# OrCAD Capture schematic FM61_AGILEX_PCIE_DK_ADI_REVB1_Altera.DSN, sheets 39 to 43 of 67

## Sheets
39 Clock 2: size B
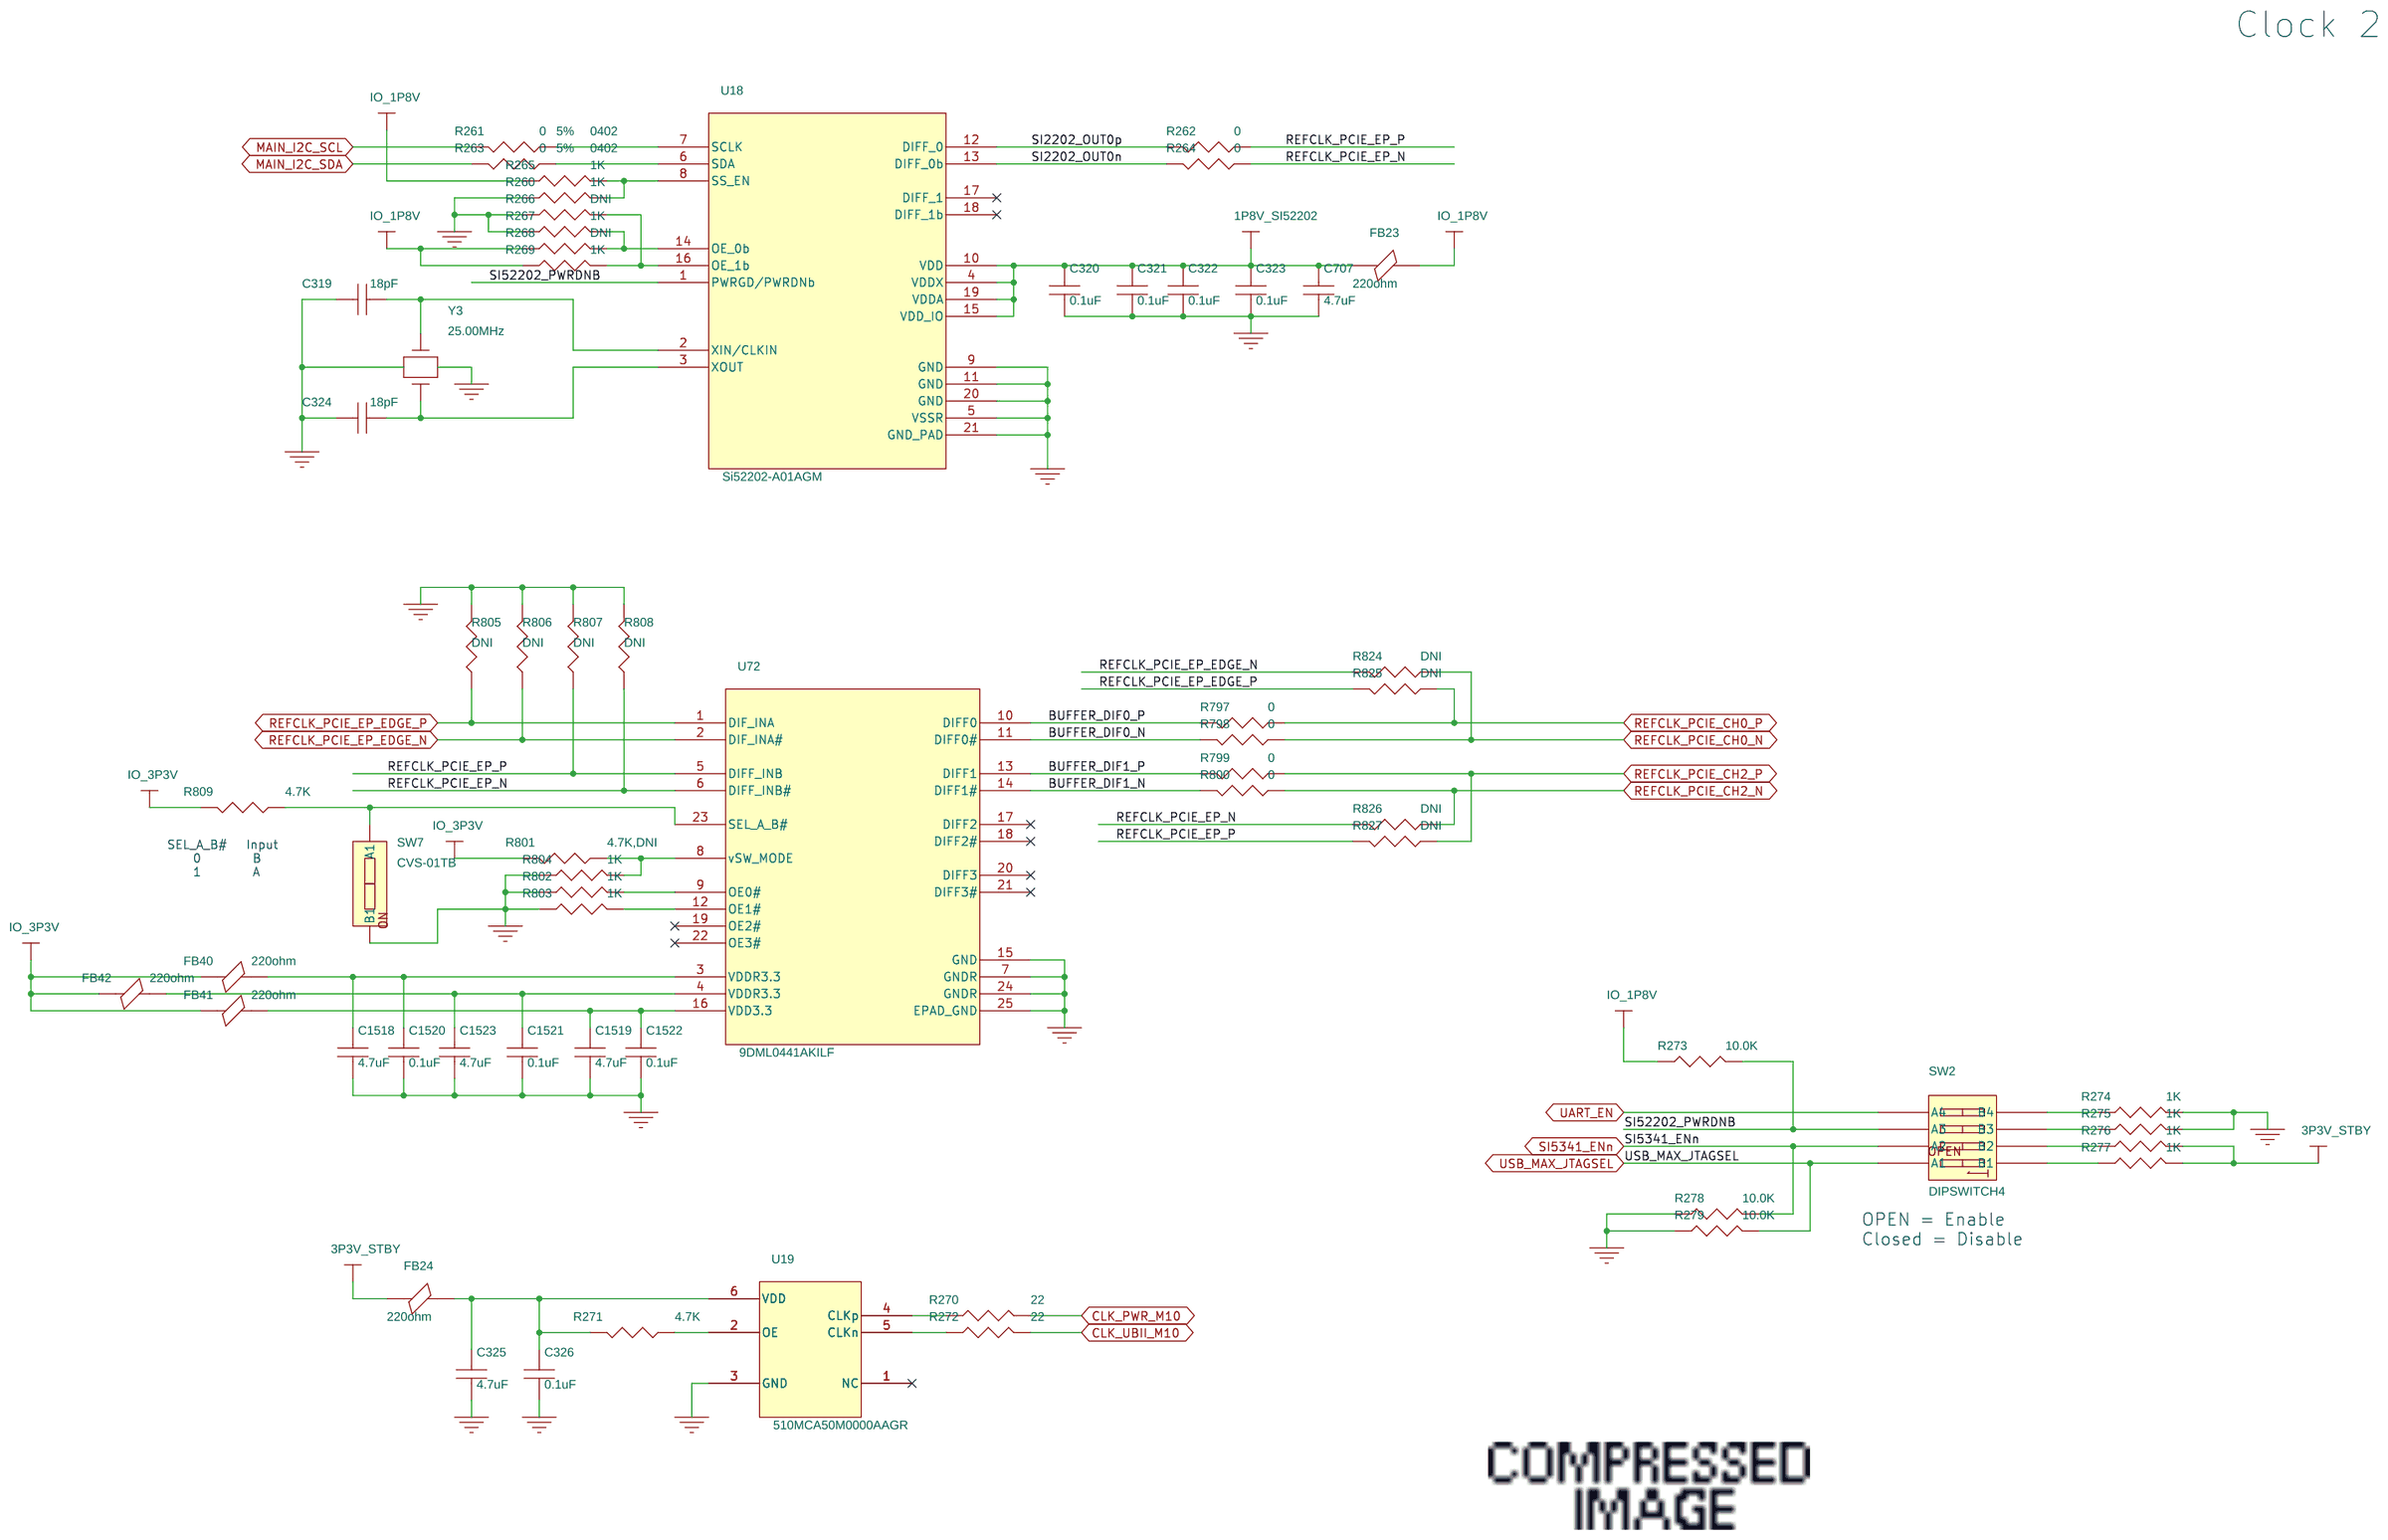
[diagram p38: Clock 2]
40 I2C And PMBUS: size B
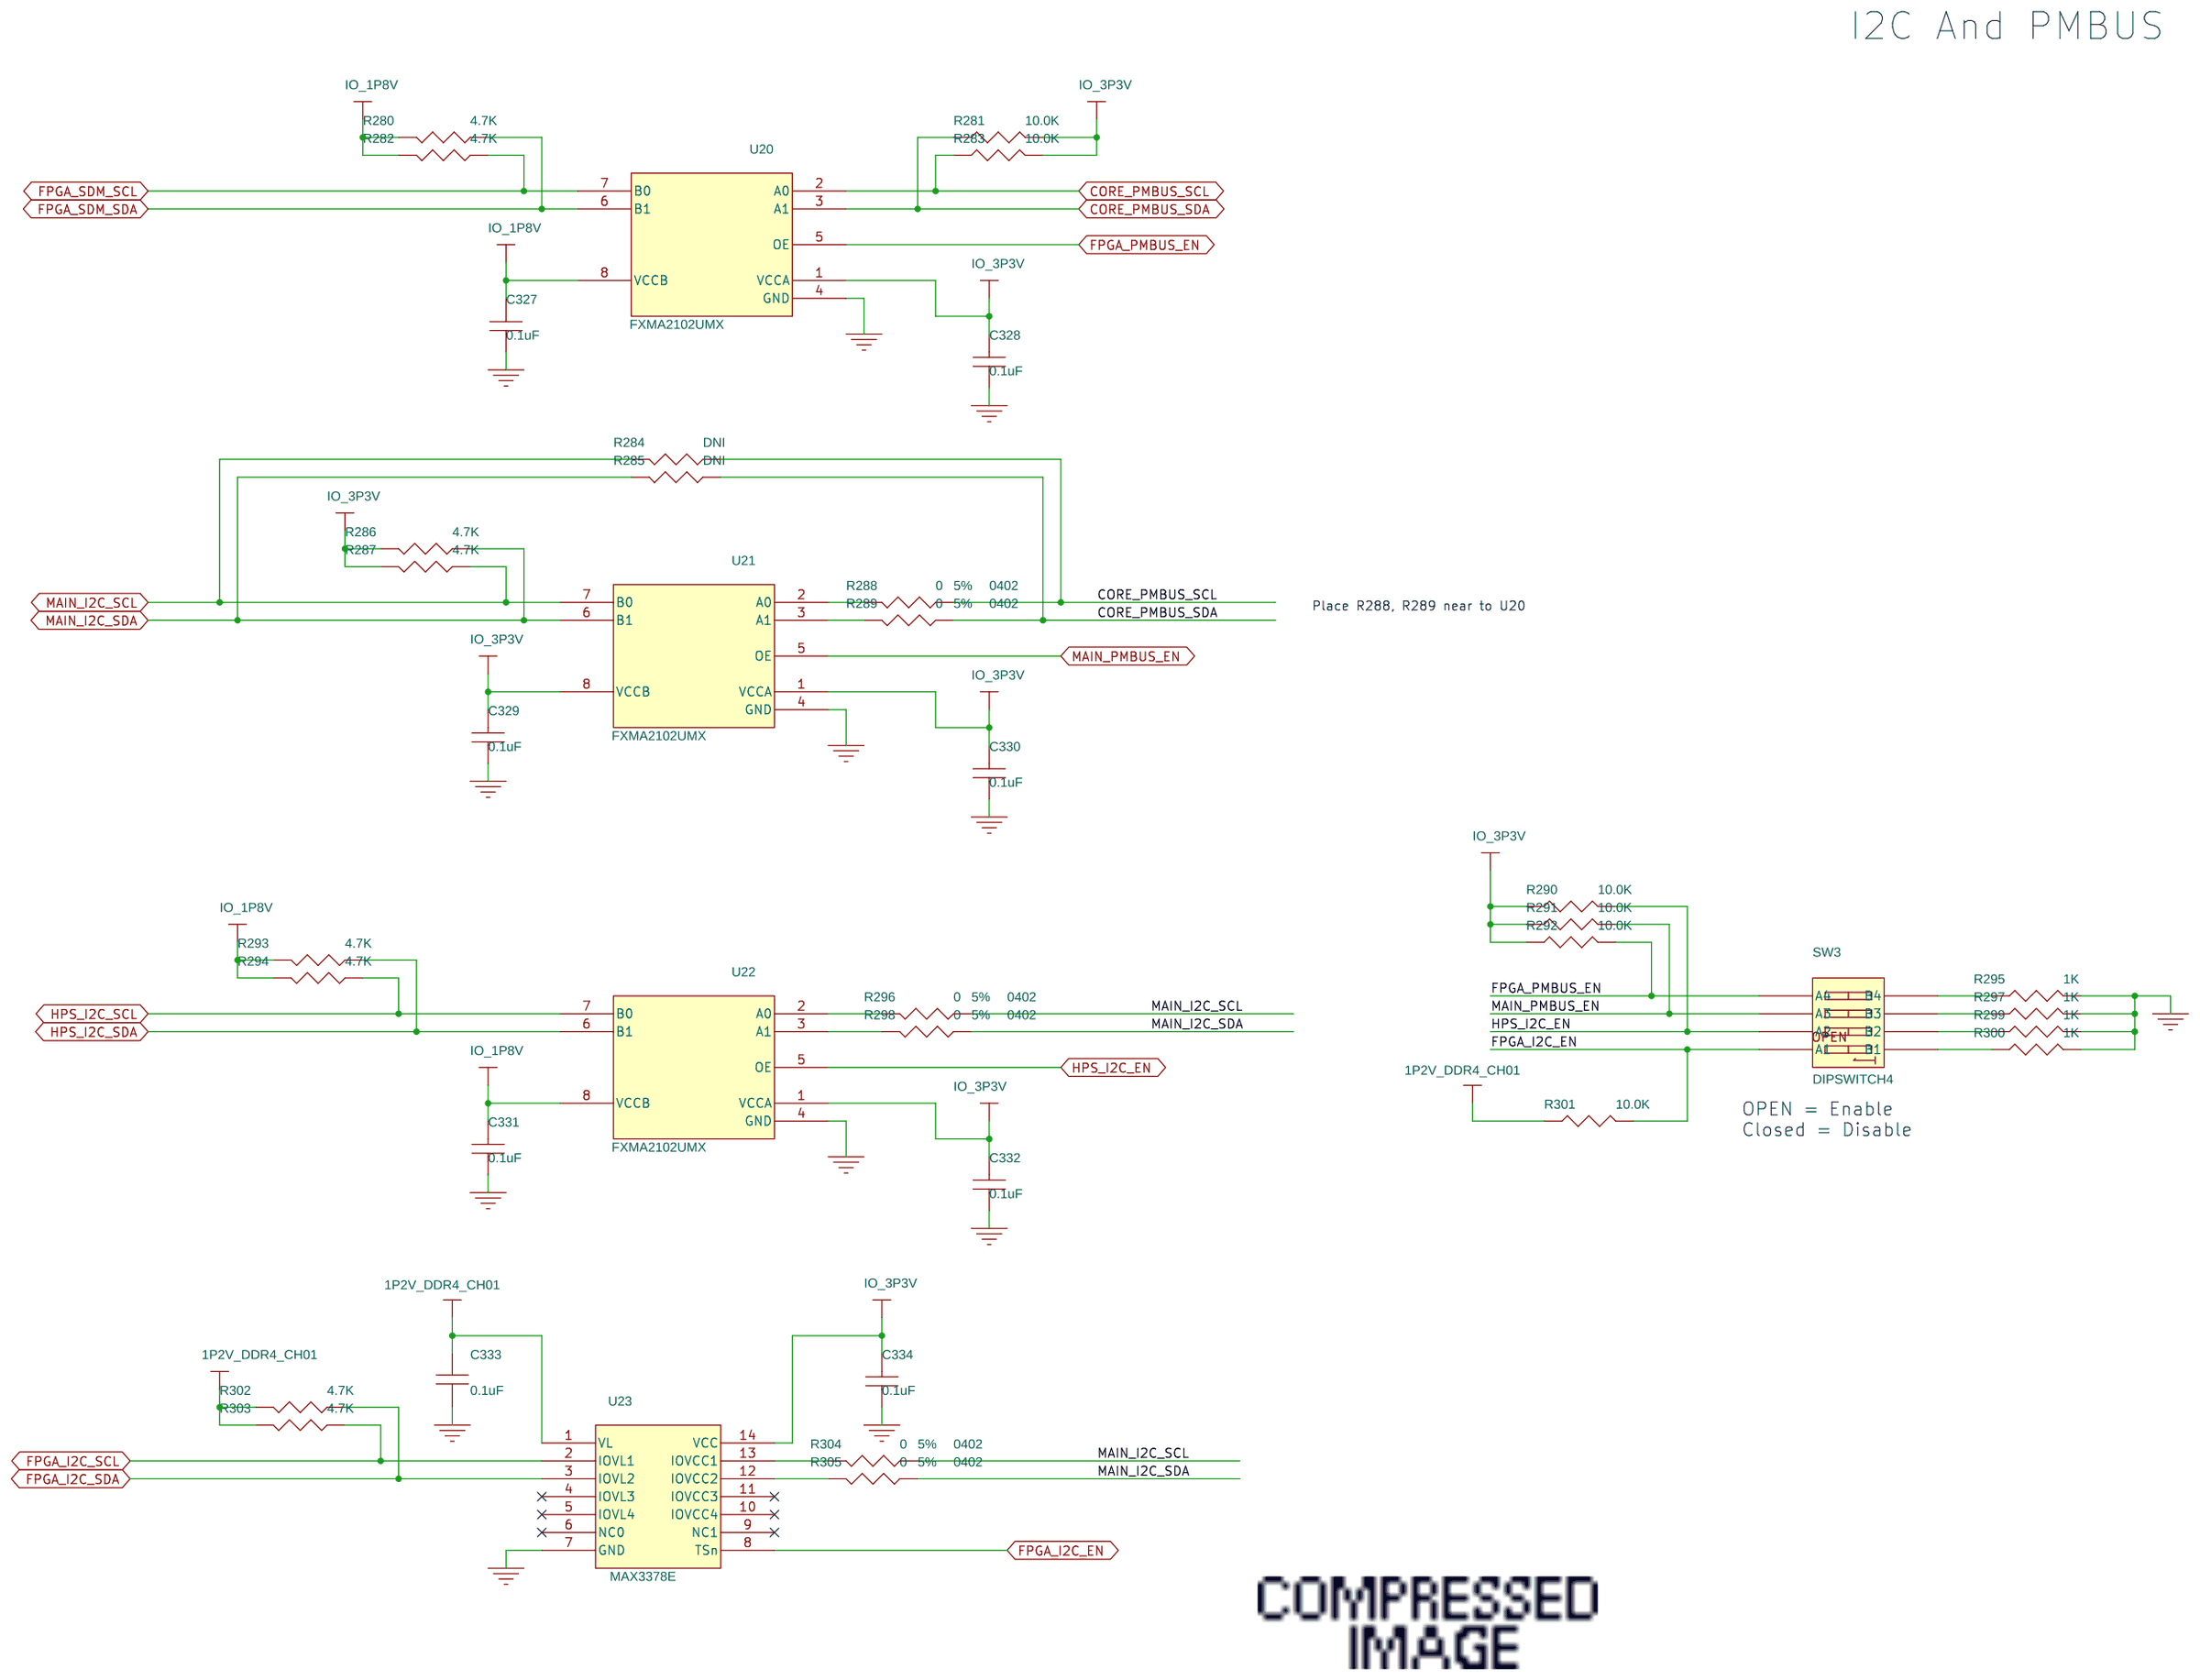
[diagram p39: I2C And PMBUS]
41 LEDs And  PushButtons: size B
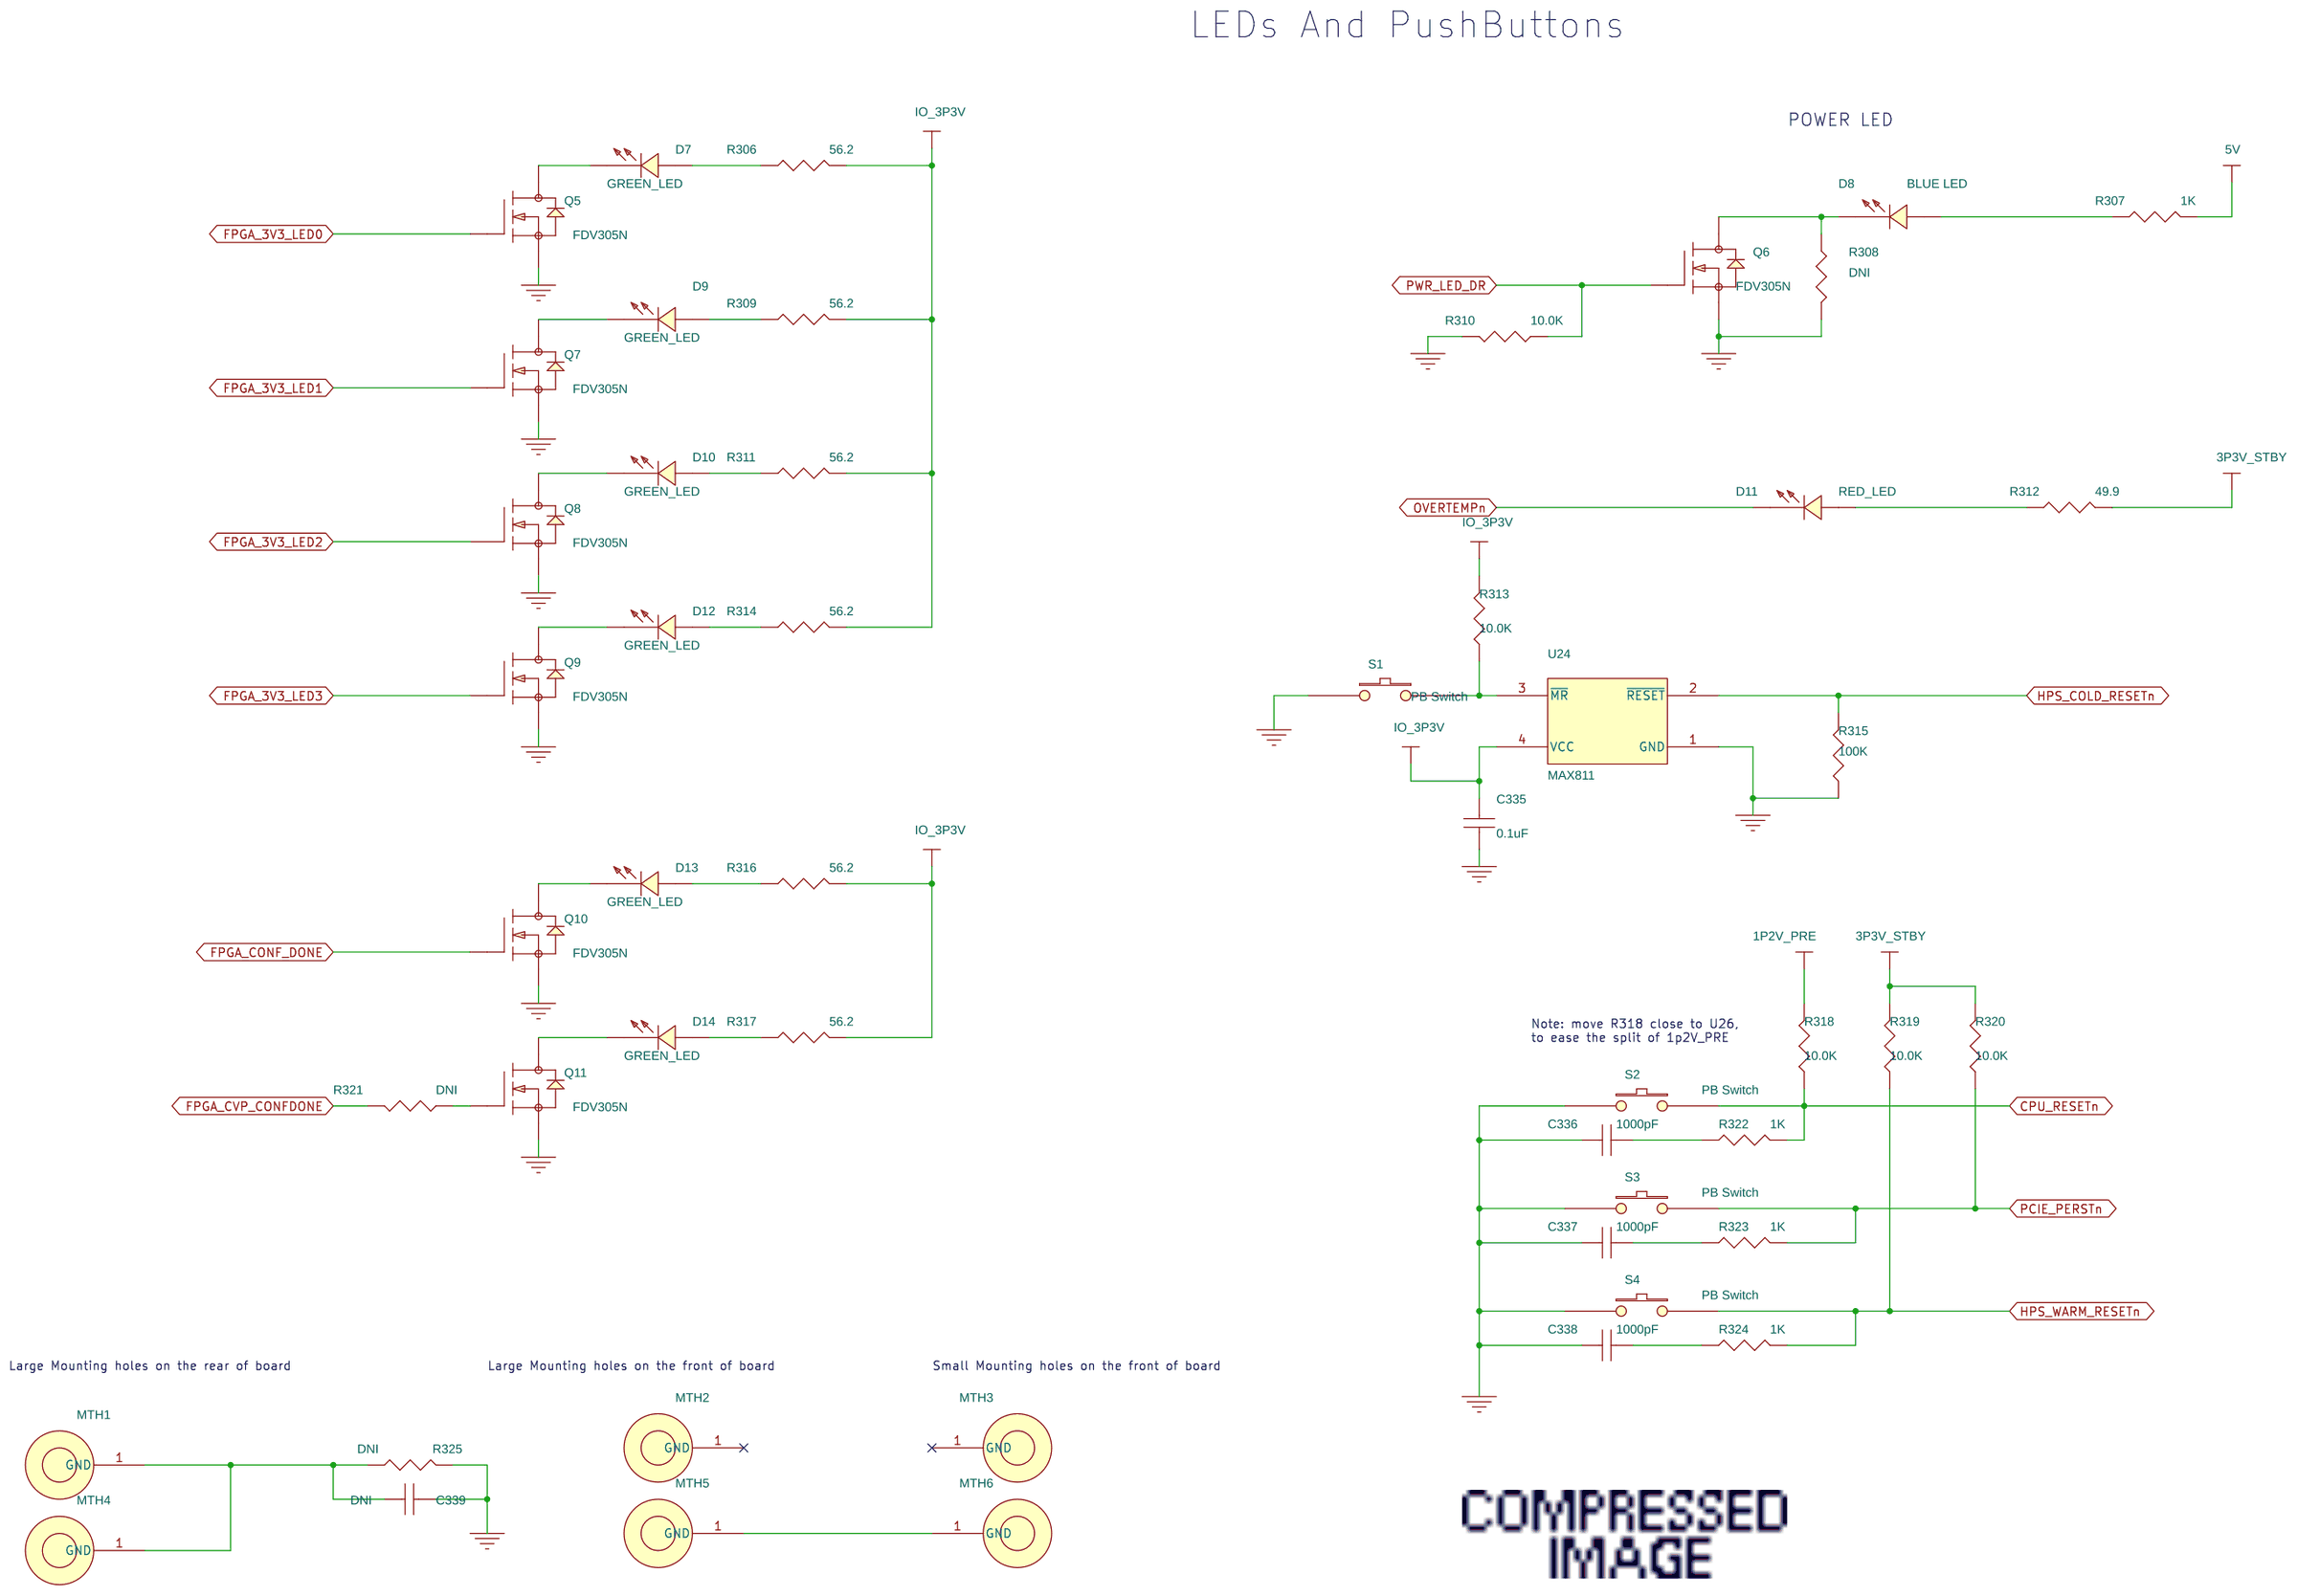
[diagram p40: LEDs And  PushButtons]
42 LEDs For QSFPDD: size B
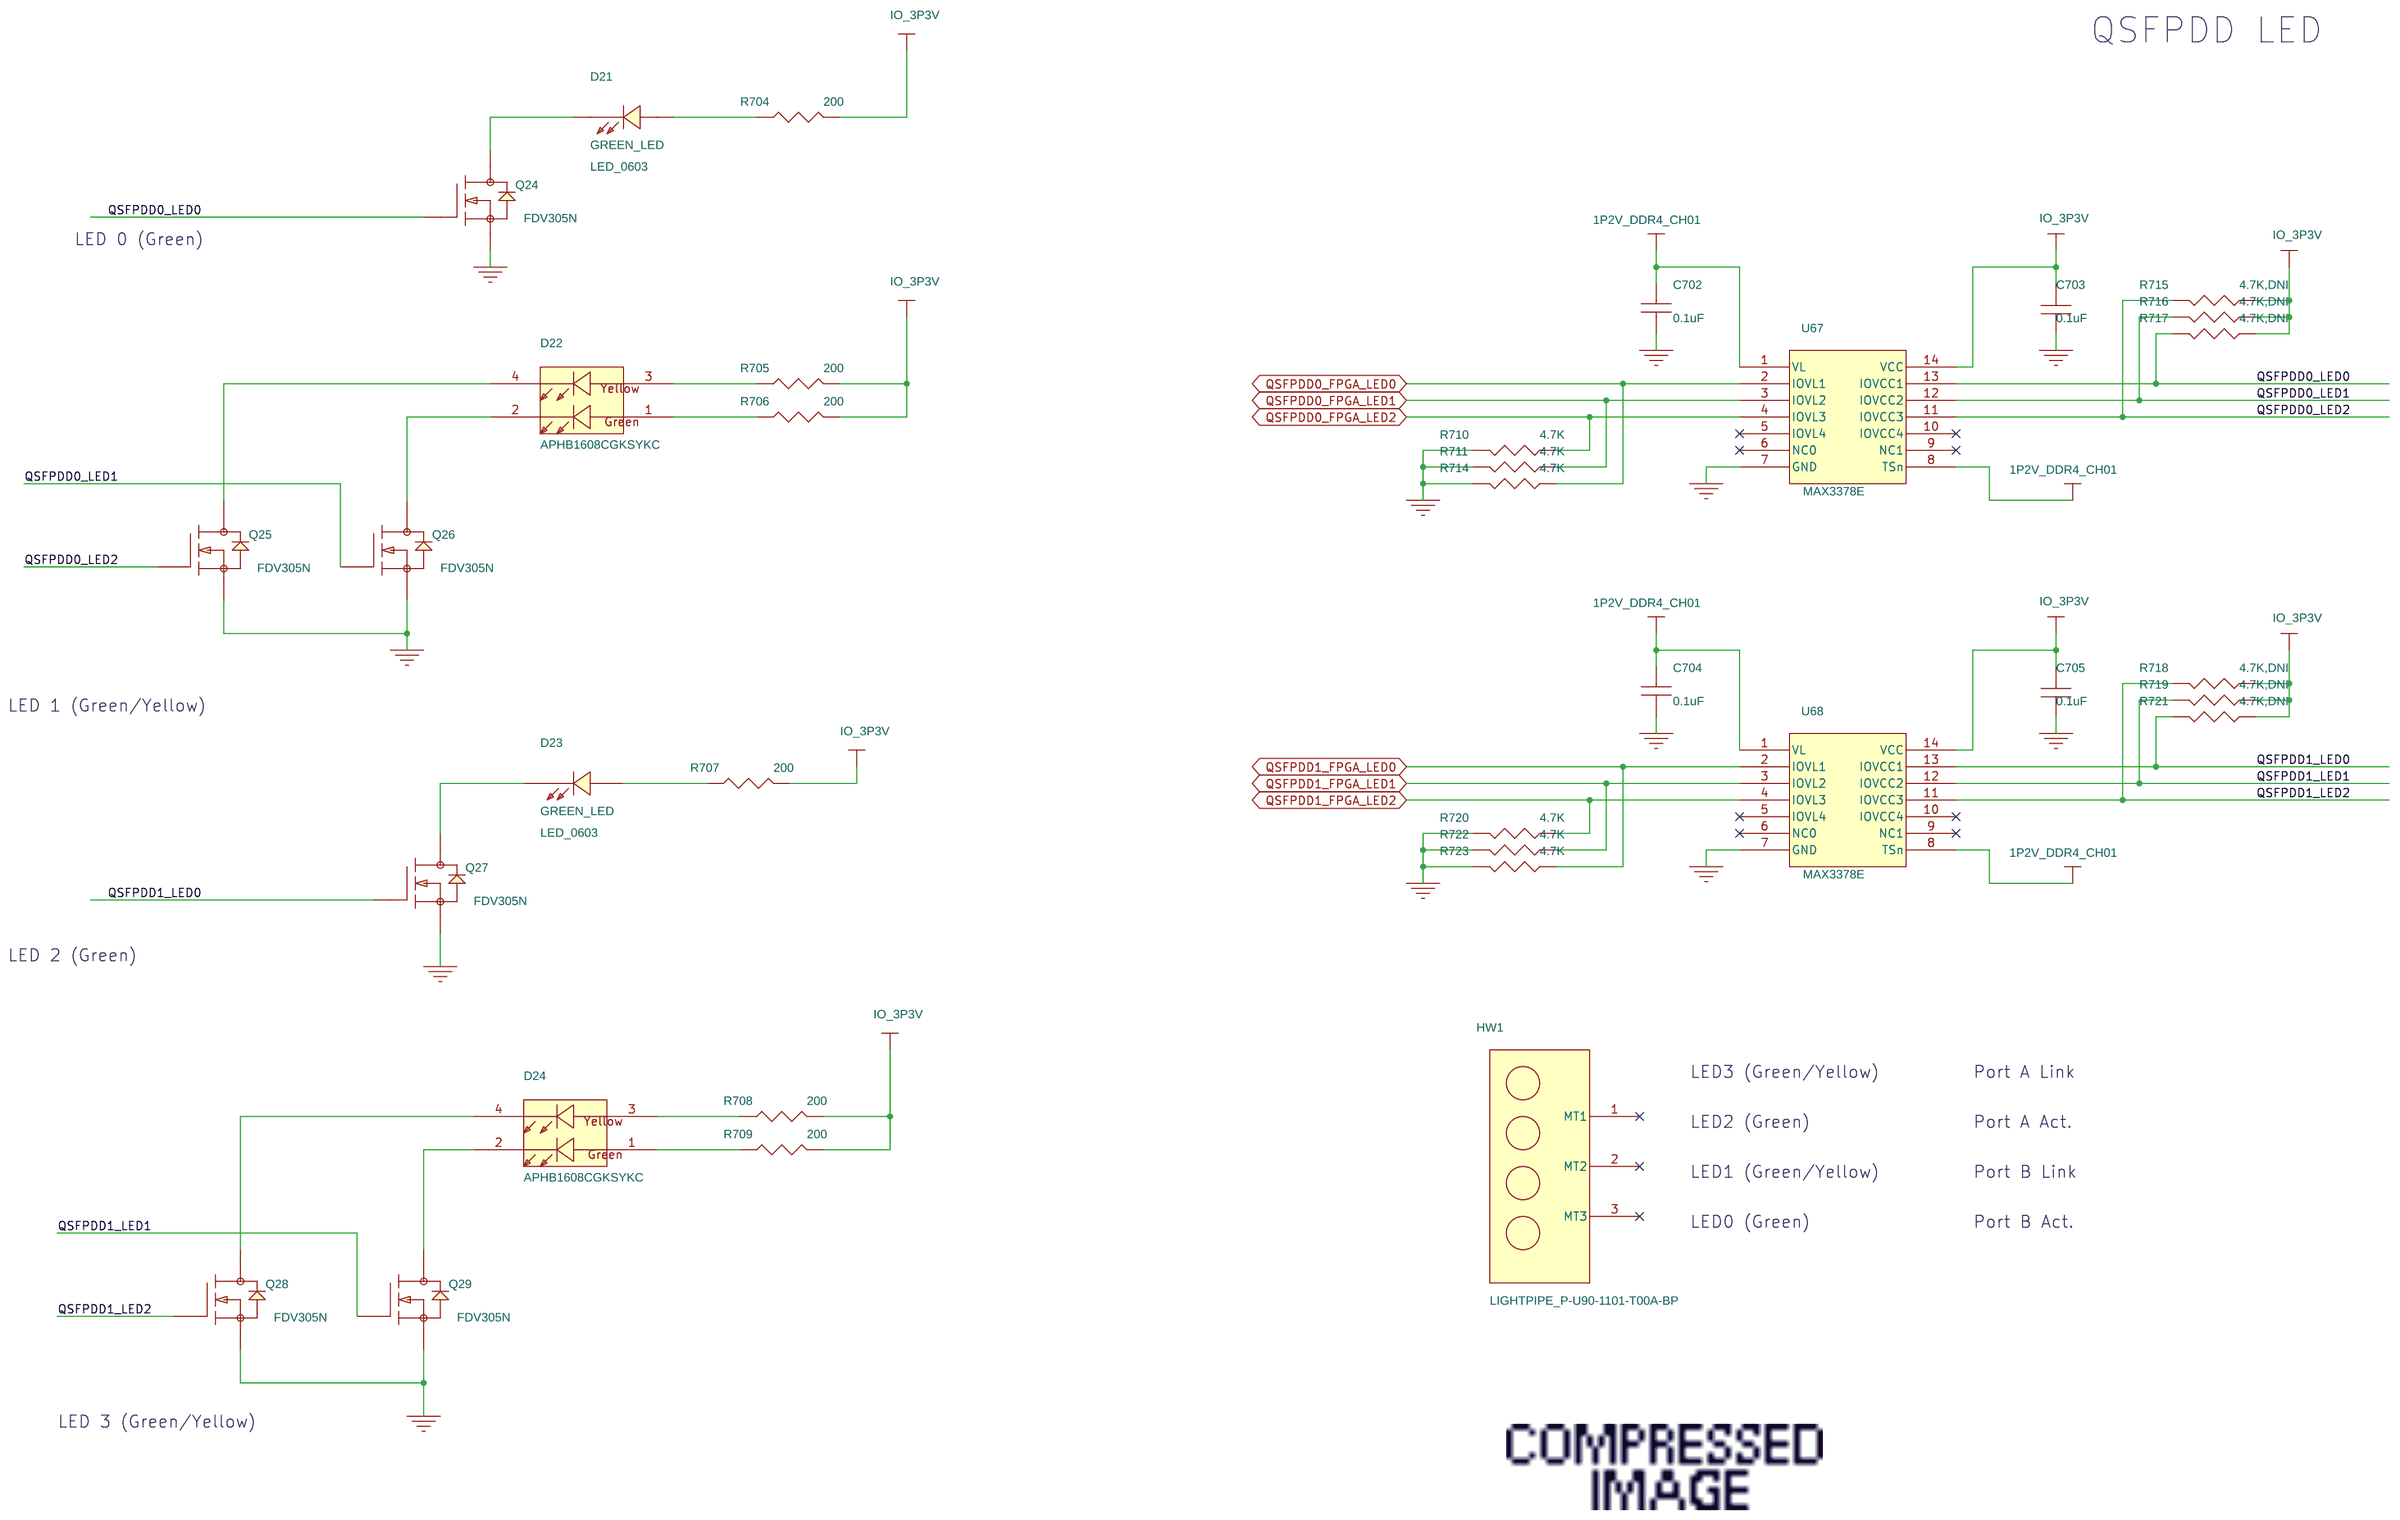
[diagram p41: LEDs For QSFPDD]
43 MAX10 - USB Blaster II -1: size B
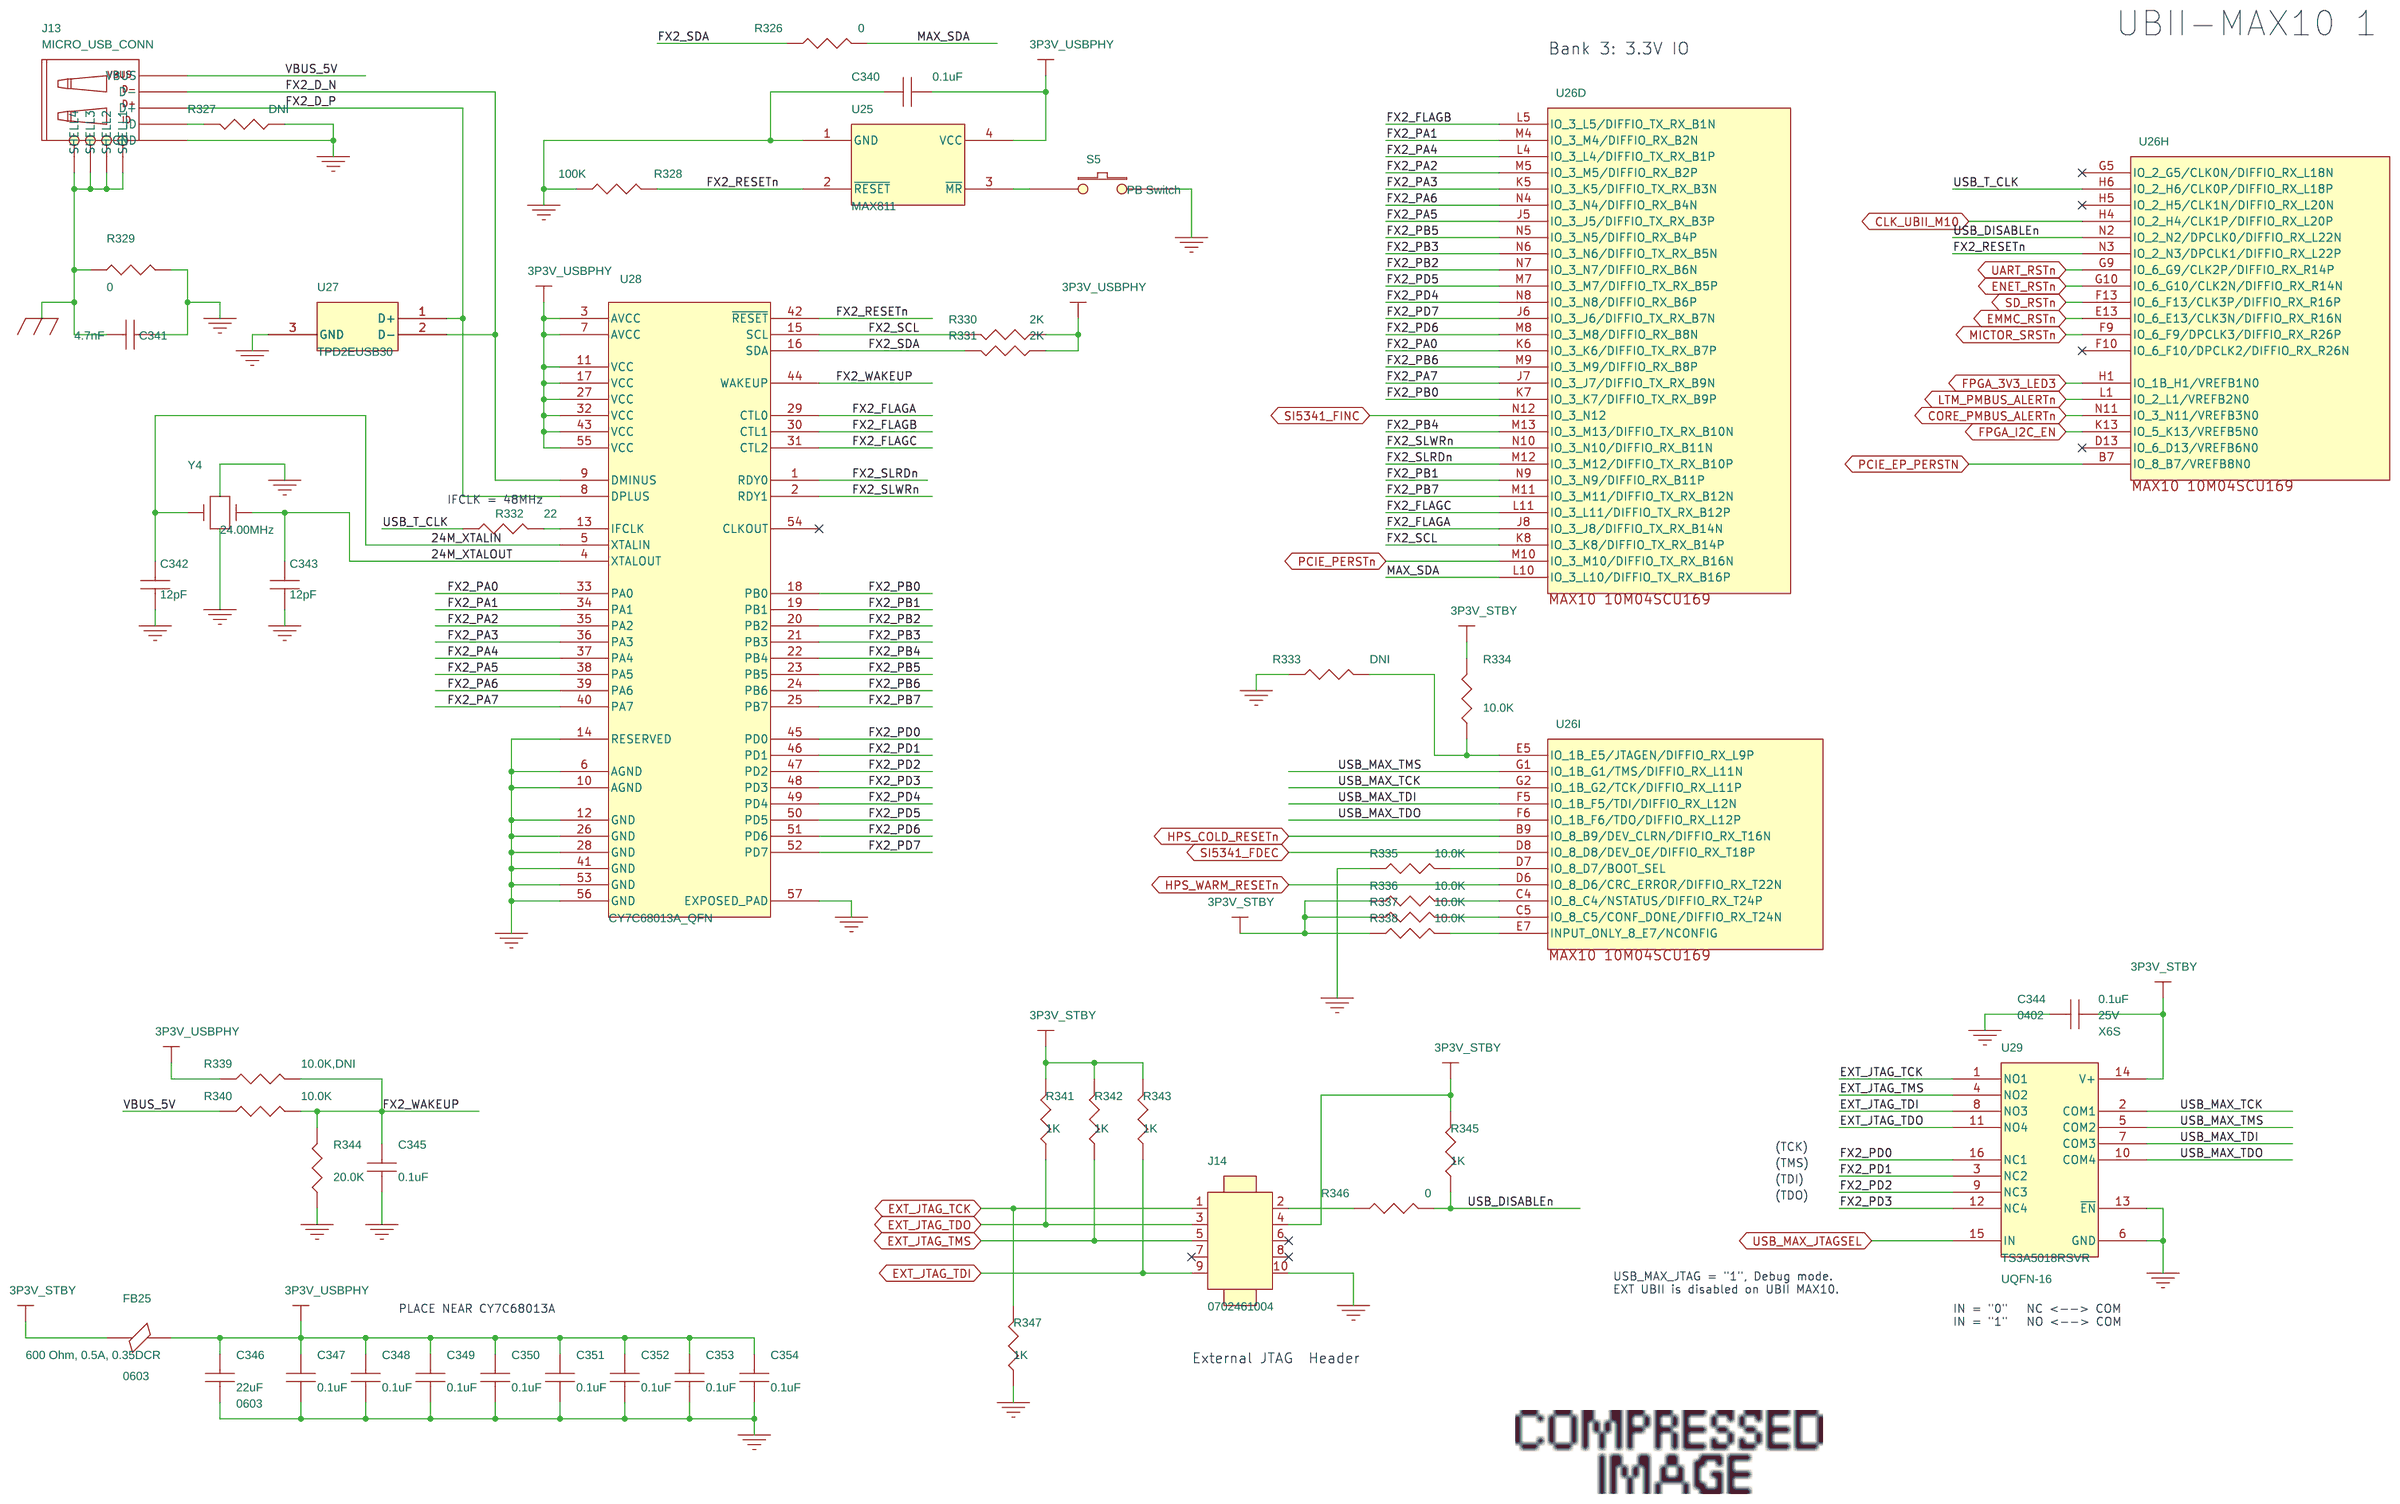
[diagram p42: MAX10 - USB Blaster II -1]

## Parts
sheet Clock 2
C319  18pF  [0402]
C320  0.1uF  [0402]
C321  0.1uF  [0402]
C322  0.1uF  [0402]
C323  0.1uF  [0402]
C324  18pF  [0402]
C325  4.7uF  [0402]
C326  0.1uF  [0402]
C707  4.7uF  [0402]
C1518  4.7uF  [0402]
C1519  4.7uF  [0402]
C1520  0.1uF  [0402]
C1521  0.1uF  [0402]
C1522  0.1uF  [0402]
C1523  4.7uF  [0402]
FB23  220ohm  [0402]
FB24  220ohm  [0402]
FB40  220ohm  [0402]
FB41  220ohm  [0402]
FB42  220ohm  [0402]
R260  1K  [0402]
R261  0  [0402]
R262  0  [0402]
R263  0  [0402]
R264  0  [0402]
R265  1K  [0402]
R266  DNI  [0402]
R267  1K  [0402]
R268  DNI  [0402]
R269  1K  [0402]
R270  22  [0402]
R271  4.7K  [0402]
R272  22  [0402]
R273  10.0K  [0402]
R274  1K  [0402]
R275  1K  [0402]
R276  1K  [0402]
R277  1K  [0402]
R278  10.0K  [0402]
R279  10.0K  [0402]
R797  0  [0402]
R798  0  [0402]
R799  0  [0402]
R800  0  [0402]
R801  4.7K,DNI  [0402]
R802  1K  [0402]
R803  1K  [0402]
R804  1K  [0402]
R805  DNI  [0402]
R806  DNI  [0402]
R807  DNI  [0402]
R808  DNI  [0402]
R809  4.7K  [0402]
R824  DNI  [0402]
R825  DNI  [0402]
R826  DNI  [0402]
R827  DNI  [0402]
SW2  DIPSWITCH4  [DIPSWITCH_SMT_QUAD]
SW7  CVS-01TB  [DIPSWITCH_SMT_SINGLE]
U18  Si52202-A01AGM  [Si52202]
U19  510MCA50M0000AAGR  [si510]
U72  9DML0441AKILF  [24-VFQFPN]
Y3  25.00MHz  [XTAL_FA-128]
sheet I2C And PMBUS
C327  0.1uF  [0402]
C328  0.1uF  [0402]
C329  0.1uF  [0402]
C330  0.1uF  [0402]
C331  0.1uF  [0402]
C332  0.1uF  [0402]
C333  0.1uF  [0402]
C334  0.1uF  [0402]
R280  4.7K  [0402]
R281  10.0K  [0402]
R282  4.7K  [0402]
R283  10.0K  [0402]
R284  DNI  [0402]
R285  DNI  [0402]
R286  4.7K  [0402]
R287  4.7K  [0402]
R288  0  [0402]
R289  0  [0402]
R290  10.0K  [0402]
R291  10.0K  [0402]
R292  10.0K  [0402]
R293  4.7K  [0402]
R294  4.7K  [0402]
R295  1K  [0402]
R296  0  [0402]
R297  1K  [0402]
R298  0  [0402]
R299  1K  [0402]
R300  1K  [0402]
R301  10.0K  [0402]
R302  4.7K  [0402]
R303  4.7K  [0402]
R304  0  [0402]
R305  0  [0402]
SW3  DIPSWITCH4  [DIPSWITCH_SMT_QUAD]
U20  FXMA2102UMX  [UMLP]
U21  FXMA2102UMX  [UMLP]
U22  FXMA2102UMX  [UMLP]
U23  MAX3378E  [TSSOP-14]
sheet LEDs And  PushButtons
C335  0.1uF  [0402]
C336  1000pF  [0402]
C337  1000pF  [0402]
C338  1000pF  [0402]
C339  DNI  [1206]
D7  GREEN_LED  [LED_0603]
D8  BLUE LED  [LED_0603]
D9  GREEN_LED  [LED_0603]
D10  GREEN_LED  [LED_0603]
D11  RED_LED  [LED_0603]
D12  GREEN_LED  [LED_0603]
D13  GREEN_LED  [LED_0603]
D14  GREEN_LED  [LED_0603]
MTH1  MT_HOLE_GND  [MH_D125C175T_TB315]
MTH2  MT_HOLE_GND  [MH_D125C175T_TB315]
MTH3  MT_HOLE_GND  [MT_HOLE]
MTH4  MT_HOLE_GND  [MH_D125C175T_TB315]
MTH5  MT_HOLE_GND  [MH_D125C175T_TB315]
MTH6  MT_HOLE_GND  [MT_HOLE]
Q5  FDV305N  [SOT23]
Q6  FDV305N  [SOT23]
Q7  FDV305N  [SOT23]
Q8  FDV305N  [SOT23]
Q9  FDV305N  [SOT23]
Q10  FDV305N  [SOT23]
Q11  FDV305N  [SOT23]
R306  56.2  [0402]
R307  1K  [0402]
R308  DNI  [0402]
R309  56.2  [0402]
R310  10.0K  [0402]
R311  56.2  [0402]
R312  49.9  [0402]
R313  10.0K  [0402]
R314  56.2  [0402]
R315  100K  [0402]
R316  56.2  [0402]
R317  56.2  [0402]
R318  10.0K  [0402]
R319  10.0K  [0402]
R320  10.0K  [0402]
R321  DNI  [0402]
R322  1K  [0402]
R323  1K  [0402]
R324  1K  [0402]
R325  DNI  [0402]
S1  PB Switch  [WURTH_6X3P5_TACT_SWITCH]
S2  PB Switch  [WURTH_6X3P5_TACT_SWITCH]
S3  PB Switch  [WURTH_6X3P5_TACT_SWITCH]
S4  PB Switch  [WURTH_6X3P5_TACT_SWITCH]
U24  MAX811  [SOT-143]
sheet LEDs For QSFPDD
C702  0.1uF  [0402]
C703  0.1uF  [0402]
C704  0.1uF  [0402]
C705  0.1uF  [0402]
D21  GREEN_LED  [LED_0603]
D22  APHB1608CGKSYKC  [LED0603_4Pin_APHB1608]
D23  GREEN_LED  [LED_0603]
D24  APHB1608CGKSYKC  [LED0603_4Pin_APHB1608]
HW1  LIGHTPIPE_P-U90-1101-T00A-BP  [LIGHTPIPE_P-U90-1101-T00A-BP]
Q24  FDV305N  [SOT23]
Q25  FDV305N  [SOT23]
Q26  FDV305N  [SOT23]
Q27  FDV305N  [SOT23]
Q28  FDV305N  [SOT23]
Q29  FDV305N  [SOT23]
R704  200  [0402]
R705  200  [0402]
R706  200  [0402]
R707  200  [0402]
R708  200  [0402]
R709  200  [0402]
R710  4.7K  [0402]
R711  4.7K  [0402]
R714  4.7K  [0402]
R715  4.7K,DNI  [0402]
R716  4.7K,DNI  [0402]
R717  4.7K,DNI  [0402]
R718  4.7K,DNI  [0402]
R719  4.7K,DNI  [0402]
R720  4.7K  [0402]
R721  4.7K,DNI  [0402]
R722  4.7K  [0402]
R723  4.7K  [0402]
U67  MAX3378E  [TSSOP-14]
U68  MAX3378E  [TSSOP-14]
sheet MAX10 - USB Blaster II -1
C340  0.1uF  [0402]
C341  4.7nF  [0402]
C342  12pF  [0402]
C343  12pF  [0402]
C344  0.1uF  [0402]
C345  0.1uF  [0402]
C346  22uF  [0603]
C347  0.1uF  [0402]
C348  0.1uF  [0402]
C349  0.1uF  [0402]
C350  0.1uF  [0402]
C351  0.1uF  [0402]
C352  0.1uF  [0402]
C353  0.1uF  [0402]
C354  0.1uF  [0402]
FB25  600 Ohm, 0.5A, 0.35DCR  [0603]
J13  MICRO_USB_CONN  [molex-micro-usb-47589-001]
J14  0702461004  [MOLEX_0702461004]
R326  0  [0402]
R327  DNI  [0402]
R328  100K  [0402]
R329  0  [0402]
R330  2K  [0402]
R331  2K  [0402]
R332  22  [0402]
R333  DNI  [0402]
R334  10.0K  [0402]
R335  10.0K  [0402]
R336  10.0K  [0402]
R337  10.0K  [0402]
R338  10.0K  [0402]
R339  10.0K,DNI  [0402]
R340  10.0K  [0402]
R341  1K  [0402]
R342  1K  [0402]
R343  1K  [0402]
R344  20.0K  [0402]
R345  1K  [0402]
R346  0  [0402]
R347  1K  [0402]
S5  PB Switch  [WURTH_6X3P5_TACT_SWITCH]
U25  MAX811  [SOT-143]
U26  10M04SCU169  [BGA169-0R80-11X11]  (sections A,B,C,D,E,F,G,H,I,J)
U27  TPD2EUSB30  [DRT]
U28  CY7C68013A_QFN  [QFN56]
U29  TS3A5018RSVR  [UQFN-16]
Y4  24.00MHz  [XTAL_FA-128]

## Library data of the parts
C319 C324 = CAP: CAP - CERAMIC, 18PF, 5%, 50V, 0402, NPO; AGILE_LINK: http://sj-agile9app/Agile/PLMServlet?action=OpenEmailObject&classid=10000&objid=213459014; IPN: H90899-001; Item Num: P03-15092R; Lead Free Status: Lead Free; MFR_LIFECYCLE: Active; Manufacturer: Panasonic; Manufacturer Part Num: ECJ-0EC1H180J; Num Pins: 2; PART_SUBCLASS: CAPACITORS; RoHS Compliant: Yes
C320-C323 C335 C345 C347-C354 = CAP: CAPC,Y5V,0402,0.1UF,25V,+80/-20%; AGILE_LINK: http://sj-agile9app/Agile/PLMServlet?action=OpenEmailObject&classid=10000&objid=213459527; IPN: K13560-001; Item Num: P03-15057R; LIFECYCLE_PHASE: Active; Lead Free Status: Lead Free; MFR_LIFECYCLE: Active; Manufacturer: Murata; Manufacturer Part Num: GRM155F51E104ZA01D; Num Pins: 2; PART_SUBCLASS: CAPACITORS; Part Class: CAPACITORS; RATED_VOLTAGE: 25V; RoHS Compliant: RoHS Compliant; TOLERANCE: +80%/-20%
C325 C707 C1518 C1519 C1523 = CAP: CAP - CER 4.7UF, +/-20%, 6.3V, X5R, 0402; IPN: H68701-001; Item Num: P03-17432R; Manufacturer: Murata; Manufacturer Part Num: GRM155R60J475ME87D; Tolerance: +/-20%; Voltage: 6.3V
C326 C1520-C1522 = CAP: CAP CER 0.1UF 25V 20% X7R 0402; AGILE_LINK: http://sj-agile9app/Agile/PLMServlet?action=OpenEmailObject&classid=10000&objid=213459527; IPN: K13660-001; Item Num: P03-17618R; LIFECYCLE_PHASE: Active; Lead Free Status: Lead Free; MFR_LIFECYCLE: Active; Manufacturer: TDK Electronics; Manufacturer Part Num: C1005X7R1E104M; Num Pins: 2; PART_SUBCLASS: CAPACITORS; Part Class: CAPACITORS; RATED_VOLTAGE: 25V; RoHS Compliant: RoHS Compliant; TOLERANCE: +80%/-20%
FB23 FB24 FB40-FB42 = BEAD_FERRITE_SM: IND - SMD EMI FILTERS/CHIP FERRITE BEAD, 220-OHM @ 100MHZ, 0.35-OHM DCR, 0402; IPN: G79186-002; Imax (A): 300mA; Item Num: P04-17068R; Manufacturer: Wurth Elektronik; Manufacturer Part Num: 742792780; Rdc (Ohms): 350mOhm; Tolerance (%): 25%
R260 R265-R269 R274-R277 R295 R297 R299 R300 R307 R322-R324 R341-R343 R345 R347 R802-R804 = RESISTOR: RES,1.00K OHMS,1.0%,1/16W,0402; IPN: G60609-021; Item Num: P02-11372R; Lead Free Status: No; Manufacturer: Panasonic; Manufacturer Part Num: ERJ-2RKF1001X; Num Pins: 2; Part Class: Resistors
R261 R263 R288 R289 R296 R298 R304 R305 R326 R329 R346 = RESISTOR: RES ZERO OHM 1/16W 5% 0402 SMD; Altera Part No.: P02-14020R; IPN: H30887-001; Item Num: P02-14020R; Lead Free Status: No; Manufacturer: Panasonic; Manufacturer Part Num: ERJ-2GE0R00X; Num Pins: 2; Part Class: RESISTORS; RoHS Compliant: Yes; Tolerance: 5%
R262 R264 R321 R327 R797-R800 R824-R827 = RES_0_OHM_5%_1_16W_0402_SMD: IPN: H30887-001
R270 R272 R332 = RESISTOR: RES, 22 OHMS, 5%, 1/16W, 0402; AGILE_LINK: http://sj-agile9app/Agile/PLMServlet?action=OpenEmailObject&classid=10000&objid=218074840; IPN: K15613-001; Item Num: P02-14098R; LIFECYCLE_PHASE: Active; MFR_LIFECYCLE: Active; Manufacturer: NIC Components Corp.; Manufacturer Part Num: NRC04J220TRF; Num Pins: 2; PART_SUBCLASS: RESISTORS; POWER: 1/16W; RoHS Compliant: RoHS Compliant; TOLERANCE: +/-5%
R271 R280 R282 R286 R287 R293 R294 R302 R303 R710 R711 R714-R723 R801 R809 = RESISTOR: RES 4.7K OHM 1/16W 5% 0402 SMD; IPN: H30885-001; Item Num: P02-14032R; Lead Free Status: No; Manufacturer: Panasonic; Manufacturer Part Num: ERJ-2GEJ472X; Manufacturer's Part No.: ERJ-2GEJ472X; Num Pins: 2; Part Class: RESISTORS; Price: 0; RoHS Compliant: Yes
R273 R278 R279 R281 R283 R290-R292 R301 R310 R313 R318-R320 R334-R338 = RESISTOR: RES,10.0K OHMS,1.0%,1/16W, 0402; AGILE_LINK: http://sj-agile9app/Agile/PLMServlet?action=OpenEmailObject&classid=10000&objid=146548997; IPN: A93548-034; Item Num: P02-11364R; LIFECYCLE_PHASE: Active; Lead Free Status: No; MFR_LIFECYCLE: Active; Manufacturer: Panasonic; Manufacturer Part Num: ERJ-2RKF1002X; Num Pins: 2; PART_SUBCLASS: RESISTORS; POWER: 1/16W; RoHS Compliant: Yes; TOLERANCE: +/-1%
R312 R805-R808 = RESISTOR: RES, 49.9 OHMS, 1%, 1/16W, 0402; IPN: K16545-001; Item Num: P02-14101R; Lead Free Status: Yes; Manufacturer: NIC Components Corp.; Manufacturer Part Num: NRC04F49R9TRF; Num Pins: 2; Part Class: Resistors; Price: 0
SW2 SW3 = SPST4: SWITCHES - 4 POS, 8 PIN, Ultra-mini SMT Half-pitch Slider DIP Switch; AGILE_LINK: http://sj-agile9app/Agile/PLMServlet?action=OpenEmailObject&classid=10000&objid=258073635; IPN: K15518-001; Item Num: P11-24098R; LIFECYCLE_PHASE: Preliminary; Lead Free Status: Not Lead Free; MFR_LIFECYCLE: Active; Manufacturer: Wurth Electronik; Manufacturer Part Num: 416131160804; Num Pins: 8; PART_SUBCLASS: SWITCHES; RoHS Compliant: RoHS Compliant
SW7 = SPST4_0: SWITCH SLIDE DIP SPST 100MA 6V; AGILE_LINK: http://sj-agile9app/Agile/PLMServlet?action=OpenEmailObject&classid=10000&objid=258073635; Agile IPN: P11-24597R; IPN: H80030-001; LIFECYCLE_PHASE: Preliminary; Lead Free Status: Not Lead Free; MFR_LIFECYCLE: Active; Manufacturer: Nidec Copal Electronics; Num Pins: 8; PART_SUBCLASS: SWITCHES; RoHS Compliant: RoHS Compliant
U18 = Si52202-A01AGM: IPN: K45431-001
U19 = Si510-DualCMOS: OSC - 50MHZ, +/-30PPM, 3.3V, DUAL CMOS (IN PHASE), CRYSTAL OSCILLATOR, SMD; IPN: K14787-001; Item Num: P13-27235R; Manufacturer: Silicon Laboratories Inc
U72 = 9DML0451AKILF: IC,CLK_GEN,24,VFQFPN,N/A,GNRTR,N/A; IPN: K46480-001
Y3 = CRYSTAL_SM_13: CRYSTAL - MINI XTL, 25.00MHZ, FREQ +/-50PPM, RANGE +/-30PPM -20~70C, 18PF, 2.0MM X 1.6MM SMD; IPN: K21427-001; Item Num: P07-19688R; Lead Free Status: Yes; MFR_LIFECYCLE: Active; Manufacturer: Epson Toyocom; Manufacturer Part Num: FA-128 25.0000MB-C; Num Pins: 4; RoHS Compliant: Yes
C327-C332 C334 C703 C705 = CAP: CAP CER 0.1UF 25V 20% X7R 0402; IPN: K13660-001; Item Num: P03-17618R; LIFECYCLE_PHASE: Active; Lead Free Status: Lead Free; Manufacturer: TDK Electronics; Manufacturer Part Num: C1005X7R1E104M; Num Pins: 2; Part Class: CAPACITORS; Price: 0; RoHS Compliant: RoHS Compliant
C333 C702 C704 = CAP: CAPC,Y5V,0402,0.1UF,25V,+80/-20%; Dielectric: Y5V; IPN: K13560-001; Item Num: P03-15057R; LIFECYCLE_PHASE: Active; Lead Free Status: Lead Free; MFR_LIFECYCLE: Active; Manufacturer: Murata; Manufacturer Part Num: GRM155F51E104ZA01D; Num Pins: 2; PART_SUBCLASS: CAPACITORS; Part Class: CAPACITORS; RATED_VOLTAGE: 25V; RoHS Compliant: RoHS Compliant; Tolerance: +80%/-20%
R284 R285 = RESISTOR: RES ZERO OHM 1/16W 5% 0402 SMD; Altera Part No.: P02-14020R; IPN: H30887-001; Item Num: P02-14020R; Lead Free Status: No; Manufacturer: Panasonic; Manufacturer Part Num: ERJ-2GE0R00X; Num Pins: 2; Part Class: RESISTORS; Price: 0; RoHS Compliant: Yes; Tolerance: 5%
U20-U22 = FXMA2102UMX: Dual Supply, 2-Bit Voltage Translator/Buffer/Repeater/Isolator for I2C application; IPN: K64812-001; Item Num: P01-17934R; Manufacturer: Fairchild
U23 U67 U68 = MAX3378E_0: IC - QUAD LOW-VOLTAGE LEVEL TRANSLATOR, +/- 15KV, ESD-PROTECTED, 1UA, 16MBPS; IPN: C34337-001; Item Num: P01-13191R; Manufacturer: Maxim; Manufacturer Part Num: MAX3378EEUD
C336-C338 = CAP: CAP CER 1000PF 50V 10% X7R 0402; Dielectric: X7R; IPN: A36096-004; Item Num: P03-17756R; LIFECYCLE_PHASE: Active; Lead Free Status: Lead Free; Manufacturer: Yageo; Manufacturer Part Num: CC0402KRX7R9BB102; Num Pins: 2; Part Class: CAPACITORS; RATED_VOLTAGE: 50V; RoHS Compliant: RoHS Compliant; Tolerance: 10%
C339 = CAP: CAP CER 1000PF 1000V X7R 1206; AGILE_LINK: http://sj-agile9app/Agile/PLMServlet?action=OpenEmailObject&classid=10000&objid=215384813; CAPACITANCE: 1000pF; IPN: K13749-001; Item Num: P03-17910R; LIFECYCLE_PHASE: Active; Lead Free Status: Lead Free; MFR_LIFECYCLE: Active; Manufacturer: Murata; Manufacturer Part Num: GRM31BR73A102KW01L; Num Pins: 2; PACKAGING: Tape & Reel (TR); PART_SUBCLASS: CAPACITORS; RATED_VOLTAGE: 1000V; RoHS Compliant: RoHS Compliant; Supplier Part Num: GRM31BR73A102KW01L; Tolerance: +/-10%
D7 D9 D10 D12-D14 = LED_WURTH: LED - BRIGHT GREEN, VF=2V, IF=0.03A, 0603; IPN: K15375-001; Item Num: P09-21344R; LIFECYCLE_PHASE: Active; Lead Free Status: Lead Free; Manufacturer: Wurth Electroniks; Manufacturer Part Num: 150060VS75000; Num Pins: 2; PART_SUBCLASS: LEDS; Part Class: LEDS; RoHS Compliant: RoHS Compliant
D8 = LED_0: LED - BLUE, VF = 3.2V, IF = 0.03A, 0603; IPN: K15378-001; Item Num: P09-21352R; Lead Free Status: No; Manufacturer: Wurth Elektronik; Manufacturer Part Num: 150060BS75000
D11 = LED_WURTH: LED -SUPER RED, VF=1.9V, IF=0.03A, 0603; IPN: K15376-001; Item Num: P09-21345R; LIFECYCLE_PHASE: Active; Lead Free Status: Lead Free; Manufacturer: Wurth Electroniks; Manufacturer Part Num: 150060SS75000; Num Pins: 2; PART_SUBCLASS: LEDS; Part Class: LEDS; RoHS Compliant: RoHS Compliant
MTH1-MTH6 = MNT_HOLE_1
Q5 Q7-Q11 Q24-Q29 = PWRMOSFET_EN_GSD_0: IC, MOSFET, N-Channel, 20V; IPN: K21465-001; Item Num: P18-31002R; Manufacturer: Fairchild; Manufacturer Part Num: FDV305N_NL
Q6 = PWRMOSFET_EN_GSD_0: IC, MOSFET, N-Channel, 20V; IPN: K21465-001; Item Num: P18-31002R; Manufacturer: Fairchild Semiconductor
R306 R309 R311 R314 R316 R317 = RESISTOR_0: RES,56.2 OHMS,1.0%,1/16W,0402; IPN: K16543-001; IPN No: K16543-001; Item Num: P02-11370R; Lead Free Status: No; Manufacturer: Panasonic; Manufacturer Part Num: ERJ-2RKF56R2X; Num Pins: 2; Part Class: RESISTORS; Price: 0; RoHS Compliant: Yes
R308 = RESISTOR: RES ZERO OHM 1/16W 5% 0402 SMD; IPN: H30887-001; Item Num: P02-14020R; Lead Free Status: No; Manufacturer: Panasonic; Manufacturer Part Num: ERJ-2GE0R00X; Num Pins: 2; Part Class: Resistors; Price: 0; RoHS Compliant: Yes
R315 R328 = RESISTOR: RES,100K OHMS,1.0%,1/16W,0402; IPN: E86804-001; Item Num: P02-11386R; Lead Free Status: No; Manufacturer: Panasonic; Manufacturer Part Num: ERJ-2RKF1003X; Num Pins: 2; POWER: 1/16W; Part Class: Resistors; Price: 0; RoHS Compliant: Yes; TOLERANCE: +/-1%
R325 = RESISTOR: RES,1M OHMS,5.0%,1/16W,0402; AGILE_LINK: http://sj-agile9app/Agile/PLMServlet?action=OpenEmailObject&classid=10000&objid=146548997; IPN: K15866-001; Item Num: P02-11390R; LIFECYCLE_PHASE: Active; Lead Free Status: No; MFR_LIFECYCLE: Active; Manufacturer: Panasonic; Manufacturer Part Num: ERJ-2GEJ105X; Num Pins: 2; PART_SUBCLASS: RESISTORS; POWER: 1/16W; RESISTANCE: 1M; RoHS Compliant: Yes; TOLERANCE: +/-5%
S1-S5 = TS-A02SA-2-S100_0: SWITCH - PUSH BUTTON 6.0X3.5MM SND; Device: S7; IPN: K11478-001; Item Num: P23-38485R; Lead Free Status: Yes; Manufacturer: Wurth Elektroniks; Manufacturer Part Num: 434121043816; Num Pins: 2; Part Class: Switches; RoHS Compliant: Yes
U24 U25 = MAX811: IC - MPU V-MONITOR 2.93V, RESET/POWER-ON RESET, SOT143-4; IPN: D16587-001; Item Num: P01-17588R; Lead Free Status: Yes; Manufacturer: Maxim Integrated Products; Manufacturer Part Num: MAX811SEUS+T; Num Pins: 4; Part Class: ICs; RoHS Compliant: Yes
D21 D23 = LED_WURTH: LED GREEN CLEAR 0603 SMD; IPN: J48659-001; Item Num: P09-21380R; Manufacturer: Kingbright; Manufacturer Part Num: APT1608CGCK; Num Pins: 2
D22 D24 = APHB1608CGKSYKC: LED,1608,SM,GRN/YEL,V,1.00,RC,2,; IPN: G93404-001; Manufacturer: Kingbright
HW1 = LIGHTPIPE_P-U90-1101-T00A-BP_2: IPN: K33020-001; Item Num: P09-21386R; Manufacturer: Amphenol; Manufacturer Part Num: P-U90-1101-T00A-BP
R704-R709 = RESISTOR: RES 200 OHM 1/16W 5% 0402 SMD; IPN: K15618-001; Item Num: P02-14026R; Manufacturer: Panasonic; Manufacturer Part Num: ERJ-2GEJ201X; Num Pins: 2; Part Class: RESISTORS; RoHS Compliant: Yes
C340 = CAP: CAPC,Y5V,0402,0.1UF,25V,+80/-20%; Dielectric: Y5V; IPN: K13560-001; Item Num: P03-15057R; LIFECYCLE_PHASE: Active; Lead Free Status: Lead Free; MFR_LIFECYCLE: Active; Manufacturer: Murata; Manufacturer Part Num: GRM155F51E104ZA01D; Num Pins: 2; PART_SUBCLASS: CAPACITORS; Part Class: CAPACITORS; RATED_VOLTAGE: 25V; RoHS Compliant: RoHS Compliant; TOLERANCE: +80%/-20%
C341 = CAP: CAP - CER 4700PF 50V 10% X7R 0402; AGILE_LINK: http://sj-agile9app/Agile/PLMServlet?action=OpenEmailObject&classid=10000&objid=215384813; IPN: A36096-066; Item Num: P03-15074R; LIFECYCLE_PHASE: Active; Lead Free Status: Lead Free; MFR_LIFECYCLE: Active; Manufacturer: Murata; Manufacturer Part Num: GRM155R71H472KA01D; Num Pins: 2; PACKAGING: Tape & Reel (TR); PART_SUBCLASS: CAPACITORS; RATED_VOLTAGE: 50V; RoHS Compliant: RoHS Compliant; Supplier Part Num: GRM155R71H472KA01D; Tolerance: +/-10%
C342 C343 = CAP: CAP - 12PF, 50V, +/-5%, CERAMIC, 0402 SMD; AGILE_LINK: http://sj-agile9app/Agile/PLMServlet?action=OpenEmailObject&classid=10000&objid=257385742; IPN: A36095-043; IPN No: A36095-043; Item Num: P03-15352R; LIFECYCLE_PHASE: Active; Lead Free Status: Lead Free; MFR_LIFECYCLE: Active; Manufacturer: Panasonic; Manufacturer Part Num: ECJ-0EC1H120J; Num Pins: 2; PART_SUBCLASS: CAPACITORS; RATED_VOLTAGE: 50V; RoHS Compliant: RoHS Compliant; TOLERANCE: +/-5%
C344 = CAP: CAP CER 0.1UF 25V X6S 0402; Dielectric: X6S; IPN: K19434-001; IPN No: K19434-001; Item Num: P03-XXXXXR; LIFECYCLE_PHASE: Active; Lead Free Status: Lead Free; Manufacturer: Murata; Manufacturer Part Num: GRM155C81E104KA12D; Num Pins: 2; Part Class: CAPACITORS; RATED_VOLTAGE: 25V; RoHS Compliant: RoHS Compliant; Tolerance: 10%
C346 = CAP: CAP CER 22UF 6.3V X6S 0603; AGILE_LINK: http://sj-agile9app/Agile/PLMServlet?action=OpenEmailObject&classid=10000&objid=257560276; IPN: H63299-001; Item Num: P03-17963R; LIFECYCLE_PHASE: Active; Lead Free Status: Lead Free; MFR_LIFECYCLE: Active; Manufacturer: Murata; Manufacturer Part Num: GRM188C80J226ME15D; Num Pins: 2; PART_SUBCLASS: CAPACITORS; RATED_VOLTAGE: 6.3V; RoHS Compliant: RoHS Compliant; TOLERANCE: 20%; Temperature Coefficient: X6S
FB25 = BEAD_FERRITE_SM: FERRITE BEAD 600 OHM, 0.5A, 0.35 DCR, 0603 1LN; IPN: G73133-001; Item Num: P04-17224R; LIFECYCLE_PHASE: Active; MFR_LIFECYCLE: Active; Manufacturer: Murata; Manufacturer Part Num: BLM18EG601SN1D; Num Pins: 2; Part Class: Inductors; RoHS Compliant: Yes
J13 = MICRO_USB_CONN: RECEPTACLE, USB 3.0, MICRO B, R/A; IPN: G68794-001; Item Num: P23-38552R; Lead Free Status: Yes; MFR_LIFECYCLE: Active; Manufacturer: Molex; Manufacturer Part Num: 47589-0001; Num Pins: 9; Part Class: Connectors; RoHS Compliant: Yes
J14 = 0702461004: IPN: K12724-001; Manufacturer Part Num: 702461004
R330 R331 = RESISTOR: RES 2K OHM 1/16W 1% 0402 SMD; IPN: J43524-001; Item Num: P02-11376R; Lead Free Status: No; Manufacturer: Panasonic; Manufacturer Part Num: ERJ-2RKF2001X; Manufacturer's Part No.: ERJ-2RKF2001X; Num Pins: 2; Part Class: RESISTORS; Price: 0; RoHS Compliant: Yes
R333 = R: RES,1.00K OHMS,1.0%,1/16W,0402; IPN: G60609-021; Item Num: P02-14274R; Lead Free Status: Yes; Manufacturer: Vishay; Manufacturer Part Num: ERJ-2RKF1001X; Num Pins: 2; Part Class: Resistors; Price: 0; RoHS Compliant: Yes
R339 R340 = RESISTOR: RES,10.0K OHMS,1.0%,1/16W, 0402; AGILE_LINK: http://sj-agile9app/Agile/PLMServlet?action=OpenEmailObject&classid=10000&objid=146548997; IPN: A93548-034; Item Num: P02-11364R; LIFECYCLE_PHASE: Active; Lead Free Status: No; MFR_LIFECYCLE: Active; Manufacturer: Panasonic; Manufacturer Part Num: ERJ-2RKF1002X; Num Pins: 2; PART_SUBCLASS: RESISTORS; POWER: 1/16W; RESISTANCE: 10K; RoHS Compliant: Yes; TOLERANCE: +/-1%
R344 = RESISTOR: RES 20.0K OHM 1/16W 1% 0402 SMD; IPN: A78608-001; Item Num: P02-14071R; Lead Free Status: Yes; Manufacturer: Panasonic; Manufacturer Part Num: ERJ-2RKF2002X; Num Pins: 2; Part Class: RESISTORS; RoHS Compliant: Yes
U26 = 10M04SCU169: IPN: 973665
U27 = TPD2EUSB30: DIODE - FULL SPEED USB ESD SOLUTION, 2CH, SOT3; IPN: K12736-001; Item Num: P08-20777R; Lead Free Status: Yes; MFR_LIFECYCLE: Active; Manufacturer: Texas Instruments; Manufacturer Part Num: TPD2EUSB30DRxx; Num Pins: 3; Part Class: ICS; RoHS Compliant: Yes
U28 = CY7C68013A_56QFN: IC - EZ-USB FX2LP Microcontroller 400KHz, 56-QFN, 3.3V; IPN: K33816-001; Item Num: P01-17739R; Lead Free Status: Yes; Manufacturer: Cypress; Manufacturer Part Num: CY7C68013A-56LTXCx; Num Pins: 57; Part Class: ICs; RoHS Compliant: Yes
U29 = TS3A5018RSVR_0: IPN: H28953-001
Y4 = CRYSTAL_SM_13: CRYSTAL - MINI XTL, 24.00 MHZ, +/-50PPM, +/-30PPM-20~75C, 12PF, 2.0mm x 1.6mm SMD; IPN: K15535-001; Item Num: P07-19648R; Lead Free Status: Yes; MFR_LIFECYCLE: Active; Manufacturer: Epson Toyocom; Manufacturer Part Num: FA-128 24.0000MB-W:; Num Pins: 4; RoHS Compliant: Yes

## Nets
5V: R307.1 ; also on sheet 49 54 63
GND: C319.2 C320.2 C321.2 C322.2 C323.2 C324.2 C325.2 C326.2 C327.1 C328.1 C329.1 C330.1 C331.1 C332.1 C333.2 C334.1 C335.2 C336.1 C337.1 C338.1 C339.2 C340.1 C341.2 C342.2 C343.2 C344.2 C345.2 C346.2 C347.2 C348.2 C349.2 C350.2 C351.2 C352.2 C353.2 C354.2 C702.2 C703.1 C704.2 C705.1 C707.2 C1518.2 C1519.2 C1520.2 C1521.2 C1522.2 C1523.2 J13.5(GND) J14.10 Q5.2(SOURCE) Q6.2(SOURCE) Q7.2(SOURCE) Q8.2(SOURCE) Q9.2(SOURCE) Q10.2(SOURCE) Q11.2(SOURCE) Q24.2(SOURCE) Q25.2(SOURCE) Q26.2(SOURCE) Q27.2(SOURCE) Q28.2(SOURCE) Q29.2(SOURCE) R260.2 R266.2 R267.2 R274.1 R275.1 R278.1 R279.1 R295.1 R297.1 R299.1 R300.1 R308.1 R310.2 R315.2 R325.1 R327.1 R328.2 R329.2 R333.1 R335.1 R344.1 R347.2 R710.2 R711.2 R714.2 R720.2 R722.2 R723.2 R802.2 R803.2 R804.2 R805.2 R806.2 R807.2 R808.2 S1.1 S2.1 S3.1 S4.1 S5.2 SW7.2(B1) U18.5(VSSR) U18.9(GND) U18.11(GND) U18.20(GND) U18.21(GND_PAD) U19.3(GND) U20.4(GND) U21.4(GND) U22.4(GND) U23.7(GND) U24.1(GND) U25.1(GND) U27.3(GND) U28.6(AGND) U28.10(AGND) U28.12(GND) U28.14(RESERVED) U28.26(GND) U28.28(GND) U28.41(GND) U28.53(GND) U28.56(GND) U28.57(EXPOSED_PAD) U29.6(GND) U29.13(~{EN}) U67.7(GND) U68.7(GND) U72.7(GNDR) U72.15(GND) U72.24(GNDR) U72.25(EPAD_GND) Y3.2 Y3.4 Y4.2 Y4.4 ; also on sheet 9 11 12 13 14 15 17 18 20 21 22 23 24 25 26 28 29 30 31 32 34 35 36 37 38 44 45 46 47 48 49 50 51 52 53 54 55 56 57 58 59 60 61 62 63 64 65 66
GND_CHS: C341.1 J13.6(SHELL1) J13.7(SHELL2) J13.8(SHELL3) J13.9(SHELL4) R329.1
VBUS_5V: J13.1(VBUS) R340.1
1p2V_DDR4_CH01: C333.1 C702.1 C704.1 R301.1 R302.2 R303.2 U23.1(VL) U67.1(VL) U67.8(TSn) U68.1(VL) U68.8(TSn) ; also on sheet 9 12 13 34 46 60 62 66
1p2V_PRE: R318.2 ; also on sheet 44 62
1p8V_SI52202: C320.1 C321.1 C322.1 C323.1 C707.1 FB23.1 U18.4(VDDX) U18.10(VDD) U18.15(VDD_IO) U18.19(VDDA)
3p3V_STBY: C344.1 FB24.1 FB25.2 J14.4 R276.1 R277.1 R312.2 R319.2 R320.2 R334.2 R336.1 R337.1 R338.1 R341.1 R342.1 R343.1 R345.1 U29.14(V+) ; also on sheet 25 44 46 47 48 49 62
3p3V_USBPHY: C340.2 C346.1 C347.1 C348.1 C349.1 C350.1 C351.1 C352.1 C353.1 C354.1 FB25.1 R330.2 R331.2 R339.1 U25.4(VCC) U28.3(AVCC) U28.7(AVCC) U28.11(VCC) U28.17(VCC) U28.27(VCC) U28.32(VCC) U28.43(VCC) U28.55(VCC)
24M_XTALIN: C342.1 U28.5(XTALIN) Y4.1
24M_XTALOUT: C343.1 U28.4(XTALOUT) Y4.3
BUFFER_DIF0_N: R798.2 U72.11(DIFF0#)
BUFFER_DIF0_P: R797.2 U72.10(DIFF0)
BUFFER_DIF1_N: R800.2 U72.14(DIFF1#)
BUFFER_DIF1_P: R799.2 U72.13(DIFF1)
CLK_PWR_M10: R270.2 ; also on sheet 47
CLK_UBII_M10: R272.2 U26.H4(IO_2_H4/CLK1P/DIFFIO_RX_L20P)
CORE_PMBUS_ALERTn: U26.N11(IO_3_N11/VREFB3N0) ; also on sheet 46 51
CORE_PMBUS_SCL: R283.1 R284.2 R288.2 U20.2(A0) ; also on sheet 51
CORE_PMBUS_SDA: R281.1 R285.2 R289.2 U20.3(A1) ; also on sheet 51
CPU_RESETn: R318.1 R322.1 S2.2 ; also on sheet 13 44
EMMC_RSTn: U26.E13(IO_6_E13/CLK3N/DIFFIO_RX_R16N) ; also on sheet 31
ENET_RSTn: U26.G10(IO_6_G10/CLK2N/DIFFIO_RX_R14N) ; also on sheet 28
EXT_JTAG_TCK: J14.1 R347.1 U29.1(NO1) ; also on sheet 44
EXT_JTAG_TDI: J14.9 R343.2 U29.8(NO3) ; also on sheet 44
EXT_JTAG_TDO: J14.3 R341.2 U29.11(NO4) ; also on sheet 44
EXT_JTAG_TMS: J14.5 R342.2 U29.4(NO2) ; also on sheet 44
FPGA_3V3_LED0: Q5.1(GATE) ; also on sheet 44
FPGA_3V3_LED1: Q7.1(GATE) ; also on sheet 44
FPGA_3V3_LED2: Q8.1(GATE) ; also on sheet 44
FPGA_3V3_LED3: Q9.1(GATE) U26.H1(IO_1B_H1/VREFB1N0)
FPGA_CONF_DONE: Q10.1(GATE) ; also on sheet 26 44
FPGA_CVP_CONFDONE: R321.2 ; also on sheet 26 44
FPGA_I2C_EN: R301.2 SW3.1(A1) U23.8(TSn) U26.K13(IO_5_K13/VREFB5N0)
FPGA_I2C_SCL: R303.1 U23.2(IOVL1) ; also on sheet 13
FPGA_I2C_SDA: R302.1 U23.3(IOVL2) ; also on sheet 13
FPGA_PMBUS_EN: R292.2 SW3.4(A4) U20.5(OE) ; also on sheet 44
FPGA_SDM_SCL: R282.1 U20.7(B0) ; also on sheet 26
FPGA_SDM_SDA: R280.1 U20.6(B1) ; also on sheet 26
FX2_D_N: J13.2(D-) U27.2(D-) U28.9(DMINUS)
FX2_D_P: J13.3(D+) U27.1(D+) U28.8(DPLUS)
FX2_FLAGA: U26.J8(IO_3_J8/DIFFIO_TX_RX_B14N) U28.29(CTL0)
FX2_FLAGB: U26.L5(IO_3_L5/DIFFIO_TX_RX_B1N) U28.30(CTL1)
FX2_FLAGC: U26.L11(IO_3_L11/DIFFIO_TX_RX_B12P) U28.31(CTL2)
FX2_PA0: U26.K6(IO_3_K6/DIFFIO_TX_RX_B7P) U28.33(PA0)
FX2_PA1: U26.M4(IO_3_M4/DIFFIO_RX_B2N) U28.34(PA1)
FX2_PA2: U26.M5(IO_3_M5/DIFFIO_RX_B2P) U28.35(PA2)
FX2_PA3: U26.K5(IO_3_K5/DIFFIO_TX_RX_B3N) U28.36(PA3)
FX2_PA4: U26.L4(IO_3_L4/DIFFIO_TX_RX_B1P) U28.37(PA4)
FX2_PA5: U26.J5(IO_3_J5/DIFFIO_TX_RX_B3P) U28.38(PA5)
FX2_PA6: U26.N4(IO_3_N4/DIFFIO_RX_B4N) U28.39(PA6)
FX2_PA7: U26.J7(IO_3_J7/DIFFIO_TX_RX_B9N) U28.40(PA7)
FX2_PB0: U26.K7(IO_3_K7/DIFFIO_TX_RX_B9P) U28.18(PB0)
FX2_PB1: U26.N9(IO_3_N9/DIFFIO_RX_B11P) U28.19(PB1)
FX2_PB2: U26.N7(IO_3_N7/DIFFIO_RX_B6N) U28.20(PB2)
FX2_PB3: U26.N6(IO_3_N6/DIFFIO_TX_RX_B5N) U28.21(PB3)
FX2_PB4: U26.M13(IO_3_M13/DIFFIO_TX_RX_B10N) U28.22(PB4)
FX2_PB5: U26.N5(IO_3_N5/DIFFIO_RX_B4P) U28.23(PB5)
FX2_PB6: U26.M9(IO_3_M9/DIFFIO_RX_B8P) U28.24(PB6)
FX2_PB7: U26.M11(IO_3_M11/DIFFIO_TX_RX_B12N) U28.25(PB7)
FX2_PD0: U28.45(PD0) U29.16(NC1)
FX2_PD1: U28.46(PD1) U29.3(NC2)
FX2_PD2: U28.47(PD2) U29.9(NC3)
FX2_PD3: U28.48(PD3) U29.12(NC4)
FX2_PD4: U26.N8(IO_3_N8/DIFFIO_RX_B6P) U28.49(PD4)
FX2_PD5: U26.M7(IO_3_M7/DIFFIO_TX_RX_B5P) U28.50(PD5)
FX2_PD6: U26.M8(IO_3_M8/DIFFIO_RX_B8N) U28.51(PD6)
FX2_PD7: U26.J6(IO_3_J6/DIFFIO_TX_RX_B7N) U28.52(PD7)
FX2_RESETn: R328.1 U25.2(~{RESET}) U26.N3(IO_2_N3/DPCLK1/DIFFIO_RX_L22P) U28.42(~{RESET})
FX2_SCL: R330.1 U26.K8(IO_3_K8/DIFFIO_TX_RX_B14P) U28.15(SCL)
FX2_SDA: R326.1 R331.1 U28.16(SDA)
FX2_SLRDn: U26.M12(IO_3_M12/DIFFIO_TX_RX_B10P) U28.1(RDY0)
FX2_SLWRn: U26.N10(IO_3_N10/DIFFIO_RX_B11N) U28.2(RDY1)
FX2_WAKEUP: C345.1 R339.2 R340.2 R344.2 U28.44(WAKEUP)
HPS_COLD_RESETn: R315.1 U24.2(~{RESET}) U26.B9(IO_8_B9/DEV_CLRN/DIFFIO_RX_T16N)
HPS_I2C_EN: R290.2 SW3.2(A2) U22.5(OE) ; also on sheet 44
HPS_I2C_SCL: R294.1 U22.7(B0) ; also on sheet 27
HPS_I2C_SDA: R293.1 U22.6(B1) ; also on sheet 27
HPS_WARM_RESETn: R319.1 R324.1 S4.2 U26.D6(IO_8_D6/CRC_ERROR/DIFFIO_RX_T22N)
IO_1p8V: C327.2 C331.2 FB23.2 R265.2 R268.2 R269.2 R273.1 R280.2 R282.2 R293.2 R294.2 U20.8(VCCB) U22.8(VCCB) ; also on sheet 26 28 29 30 31 34 38 46 57 65
IO_3p3V: C328.2 C329.2 C330.2 C332.2 C334.2 C335.1 C703.2 C705.2 FB40.1 FB41.1 FB42.1 R281.2 R283.2 R286.2 R287.2 R290.1 R291.1 R292.1 R306.2 R309.2 R311.2 R313.2 R314.2 R316.2 R317.2 R704.2 R705.2 R706.2 R707.2 R708.2 R709.2 R715.1 R716.1 R717.1 R718.1 R719.1 R721.1 R801.2 R809.2 U20.1(VCCA) U21.1(VCCA) U21.8(VCCB) U22.1(VCCA) U23.14(VCC) U24.4(VCC) U67.14(VCC) U68.14(VCC) ; also on sheet 12 23 24 25 28 30 31 38 63
LTM_PMBUS_ALERTn: U26.L1(IO_2_L1/VREFB2N0) ; also on sheet 46 54 58
MAIN_I2C_SCL: R261.1 R284.1 R287.1 R296.2 R304.2 U21.7(B0) ; also on sheet 38 44 46 47 54
MAIN_I2C_SDA: R263.1 R285.1 R286.1 R298.2 R305.2 U21.6(B1) ; also on sheet 38 44 46 47 54
MAIN_PMBUS_EN: R291.2 SW3.3(A3) U21.5(OE) ; also on sheet 44
MAX_SDA: R326.2 U26.L10(IO_3_L10/DIFFIO_TX_RX_B16P)
MICTOR_SRSTn: U26.F9(IO_6_F9/DPCLK3/DIFFIO_RX_R26P) ; also on sheet 30
OVERTEMPn: D11.C(CATHODE) ; also on sheet 47
PCIE_EP_PERSTN: U26.B7(IO_8_B7/VREFB8N0) ; also on sheet 25 47
PCIE_PERSTn: R320.1 R323.1 S3.2 U26.M10(IO_3_M10/DIFFIO_TX_RX_B16N)
PWR_LED_DR: Q6.1(GATE) R310.1 ; also on sheet 46
QSFPDD0_FPGA_LED0: R714.1 U67.2(IOVL1) ; also on sheet 13
QSFPDD0_FPGA_LED1: R711.1 U67.3(IOVL2) ; also on sheet 13
QSFPDD0_FPGA_LED2: R710.1 U67.4(IOVL3) ; also on sheet 13
QSFPDD0_LED0: Q24.1(GATE) R717.2 U67.13(IOVCC1)
QSFPDD0_LED1: Q26.1(GATE) R716.2 U67.12(IOVCC2)
QSFPDD0_LED2: Q25.1(GATE) R715.2 U67.11(IOVCC3)
QSFPDD1_FPGA_LED0: R723.1 U68.2(IOVL1) ; also on sheet 13
QSFPDD1_FPGA_LED1: R722.1 U68.3(IOVL2) ; also on sheet 13
QSFPDD1_FPGA_LED2: R720.1 U68.4(IOVL3) ; also on sheet 13
QSFPDD1_LED0: Q27.1(GATE) R721.2 U68.13(IOVCC1)
QSFPDD1_LED1: Q29.1(GATE) R719.2 U68.12(IOVCC2)
QSFPDD1_LED2: Q28.1(GATE) R718.2 U68.11(IOVCC3)
REFCLK_PCIE_CH0_N: R798.1 R824.1 ; also on sheet 22
REFCLK_PCIE_CH0_P: R797.1 R825.1 ; also on sheet 22
REFCLK_PCIE_CH2_N: R800.1 R826.1 ; also on sheet 22
REFCLK_PCIE_CH2_P: R799.1 R827.1 ; also on sheet 22
REFCLK_PCIE_EP_EDGE_N: R806.1 R824.2 U72.2(DIF_INA#) ; also on sheet 25
REFCLK_PCIE_EP_EDGE_P: R805.1 R825.2 U72.1(DIF_INA) ; also on sheet 25
REFCLK_PCIE_EP_N: R264.1 R808.1 R826.2 U72.6(DIFF_INB#)
REFCLK_PCIE_EP_P: R262.1 R807.1 R827.2 U72.5(DIFF_INB)
SD_RSTn: U26.F13(IO_6_F13/CLK3P/DIFFIO_RX_R16P) ; also on sheet 30
SI2202_OUT0n: R264.2 U18.13(DIFF_0b)
SI2202_OUT0p: R262.2 U18.12(DIFF_0)
SI5341_ENn: R278.2 SW2.2(A2) ; also on sheet 38 44
SI5341_FDEC: U26.D8(IO_8_D8/DEV_OE/DIFFIO_RX_T18P) ; also on sheet 38
SI5341_FINC: U26.N12(IO_3) ; also on sheet 38
SI52202_PWRDNB: R273.2 SW2.3(A3) U18.1(PWRGD/PWRDNb)
UART_EN: SW2.4(A4) ; also on sheet 29
UART_RSTn: U26.G9(IO_6_G9/CLK2P/DIFFIO_RX_R14P) ; also on sheet 29
USB_DISABLEn: R345.2 R346.2 U26.N2(IO_2_N2/DPCLK0/DIFFIO_RX_L22N)
USB_MAX_JTAGSEL: R279.2 SW2.1(A1) U29.15(IN) ; also on sheet 44
USB_MAX_TCK: U26.G2(IO_1B_G2/TCK/DIFFIO_RX_L11P) U29.2(COM1)
USB_MAX_TDI: U26.F5(IO_1B_F5/TDI/DIFFIO_RX_L12N) U29.7(COM3)
USB_MAX_TDO: U26.F6(IO_1B_F6/TDO/DIFFIO_RX_L12P) U29.10(COM4)
USB_MAX_TMS: U26.G1(IO_1B_G1/TMS/DIFFIO_RX_L11N) U29.5(COM2)
USB_T_CLK: R332.1 U26.H6(IO_2_H6/CLK0P/DIFFIO_RX_L18P)
N22385889: R333.2 R334.1 U26.E5(IO_1B_E5/JTAGEN/DIFFIO_RX_L9P)
N23293405: S5.1 U25.3(~{MR})
N31006327: J13.4(ID) R327.2
N31014989: R337.2 U26.C5(IO_8_C5/CONF_DONE/DIFFIO_RX_T24N)
N31015011: R338.2 U26.E7(INPUT_ONLY_8_E7/NCONFIG)
N31015146: R335.2 U26.D7(IO_8_D7/BOOT_SEL)
N31015158: R336.2 U26.C4(IO_8_C4/NSTATUS/DIFFIO_RX_T24P)
N31352894: R295.2 SW3.5(B4)
N31352897: R297.2 SW3.6(B3)
N31352900: R299.2 SW3.7(B2)
N31388806: D9.A(ANODE) R309.1
N31388830: D7.A(ANODE) R306.1
N31388866: D7.C(CATHODE) Q5.3(DRAIN)
N31388880: D9.C(CATHODE) Q7.3(DRAIN)
N31388890: D10.A(ANODE) R311.1
N31388919: D10.C(CATHODE) Q8.3(DRAIN)
N31389008: D12.A(ANODE) R314.1
N31389082: D12.C(CATHODE) Q9.3(DRAIN)
N31389304: D14.A(ANODE) R317.1
N31389320: D13.A(ANODE) R316.1
N31389364: D13.C(CATHODE) Q10.3(DRAIN)
N31389378: D14.C(CATHODE) Q11.3(DRAIN)
N31389867: Q11.1(GATE) R321.1
N33771526: D8.C(CATHODE) Q6.3(DRAIN) R308.2
N33771550: D8.A(ANODE) R307.2
N34054433: D11.A(ANODE) R312.1
N34315909: C336.2 R322.2
N34315982: C337.2 R323.2
N34474357: R288.1 U21.2(A0)
N34474360: R289.1 U21.3(A1)
N34525726: C339.1 MTH1.1(GND) MTH4.1(GND) R325.2
N34626400: R332.2 U28.13(IFCLK)
N34824147: MTH5.1(GND) MTH6.1(GND)
N36075384: J14.2 R346.1
N36077918: C319.1 U18.2(XIN/CLKIN) Y3.3
N36077948: C324.1 U18.3(XOUT) Y3.1
N36078275: R267.1 R268.1 U18.14(OE_0b)
N36078278: R266.1 R269.1 U18.16(OE_1b)
N36078643: R260.1 R265.1 U18.8(SS_EN)
N36079166: C325.1 C326.1 FB24.2 R271.2 U19.6(VDD)
N36079197: R270.1 U19.4(CLKp)
N36079218: R271.1 U19.2(OE)
N36079220: R272.1 U19.5(CLKn)
N36226098: C338.2 R324.2
N36270051: R304.1 U23.13(IOVCC1)
N36270054: R305.1 U23.12(IOVCC2)
N36270110: R296.1 U22.2(A0)
N36270125: R298.1 U22.3(A1)
N36270340: R300.2 SW3.8(B1)
N36272215: R313.1 S1.2 U24.3(~{MR})
N36273529: R263.2 U18.6(SDA)
N36273532: R261.2 U18.7(SCLK)
N36344563: R274.2 SW2.5(B4)
N36344586: R275.2 SW2.6(B3)
N36344607: R276.2 SW2.7(B2)
N36344628: R277.2 SW2.8(B1)
N36541668: D21.A(ANODE) R704.1
N36541743: D22.3 R705.1
N36541790: D22.1 R706.1
N36541991: D23.A(ANODE) R707.1
N36542034: D24.3 R708.1
N36542055: D24.1 R709.1
N36542312: D21.C(CATHODE) Q24.3(DRAIN)
N36542538: D22.4 Q25.3(DRAIN)
N36542543: D22.2 Q26.3(DRAIN)
N36542635: D23.C(CATHODE) Q27.3(DRAIN)
N36542846: D24.4 Q28.3(DRAIN)
N36542851: D24.2 Q29.3(DRAIN)
N37761290: R802.1 U72.9(OE0#)
N37761293: R803.1 U72.12(OE1#)
N37761614: C1518.1 C1520.1 FB40.2 U72.3(VDDR3.3)
N37761618: C1521.1 C1523.1 FB42.2 U72.4(VDDR3.3)
N37761695: C1519.1 C1522.1 FB41.2 U72.16(VDD3.3)
N37762935: R801.1 R804.1 U72.8(vSW_MODE)
N37763666: R809.1 SW7.1(A1) U72.23(SEL_A_B#)

Not connected (* = marked no-connect by the designer): HW1 1(MT1)* 2(MT2)* 3(MT3)*; J14 6* 7* 8*; MTH2 1(GND)*; MTH3 1(GND)*; U18 17(DIFF_1)* 18(DIFF_1b)*; U19 1(NC)*; U23 4(IOVL3)* 5(IOVL4)* 6(NC0)* 9(NC1)* 10(IOVCC4)* 11(IOVCC3)*; U26 D13(IO_6_D13/VREFB6N0)* F10(IO_6_F10/DPCLK2/DIFFIO_RX_R26N)* G5(IO_2_G5/CLK0N/DIFFIO_RX_L18N)* H5(IO_2_H5/CLK1N/DIFFIO_RX_L20N)*; U28 54(CLKOUT)*; U67 5(IOVL4)* 6(NC0)* 9(NC1)* 10(IOVCC4)*; U68 5(IOVL4)* 6(NC0)* 9(NC1)* 10(IOVCC4)*; U72 17(DIFF2)* 18(DIFF2#)* 19(OE2#)* 20(DIFF3)* 21(DIFF3#)* 22(OE3#)*

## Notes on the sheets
sheet 39
- Clock 2
- SEL_A_B#   Input
      0        B
      1        A
- OPEN = Enable
  Closed = Disable
sheet 40
- I2C And PMBUS
- Place R288, R289 near to U20
- OPEN = Enable
  Closed = Disable
sheet 41
- LEDs And PushButtons
- POWER LED
- Note: move R318 close to U26,
  to ease the split of 1p2V_PRE
- Large Mounting holes on the rear of board
- Large Mounting holes on the front of board
- Small Mounting holes on the front of board
sheet 42
- QSFPDD LED
- LED 0 (Green)
- LED 1 (Green/Yellow)
- LED 2 (Green)
- LED3 (Green/Yellow)
- Port A Link
- LED2 (Green)
- Port A Act.
- LED1 (Green/Yellow)
- Port B Link
- LED0 (Green)
- Port B Act.
- LED 3 (Green/Yellow)
sheet 43
- UBII-MAX10 1
- Bank 3: 3.3V IO
- IFCLK = 48MHz
- (TCK)
- (TMS)
- (TDI)
- (TDO)
- USB_MAX_JTAG = "1", Debug mode.
  EXT UBII is disabled on UBII MAX10.
- PLACE NEAR CY7C68013A
- IN = "0"   NC <--> COM
  IN = "1"   NO <--> COM
- External JTAG  Header
